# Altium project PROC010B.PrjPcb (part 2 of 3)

## Sheet PROC010C_Pwr_RST_LEDs.SchDoc: Pwr_RST_LEDs
size 431 x 279 mm; Date: Not shown in title block; ApprovedBy: Not shown in title block; CheckedBy: Not shown in title block; Author: Not shown in title block; CompanyName: Not shown in title block; DrawnBy: Adrian Ozer; Engineer: Not shown in title block; Organization: Not shown in title block; Address1: Not shown in title block; Address2: Not shown in title block; Address3: Not shown in title block; Address4: Not shown in title block; DocumentNumber: 8; Revision: Use project parameter SCH_Rev; SheetNumber: 8; SheetTotal: 16; PageSetup: Record=PageOptions¦CenterHorizontal=True¦CenterVertical=True¦PrintScale=1.00¦XCorrection=1.00¦YCorrection=1.00¦PrintKind=0¦BorderSize=5000000¦LeftOffset=0¦BottomOffset=0¦Orientation=2¦PaperLength=1000¦PaperWidth=1000¦Scale=100¦PaperSource=15¦PrintQuality=600¦MediaType=1¦DitherType=10¦PaperKind=Letter¦PrintScaleMode=1
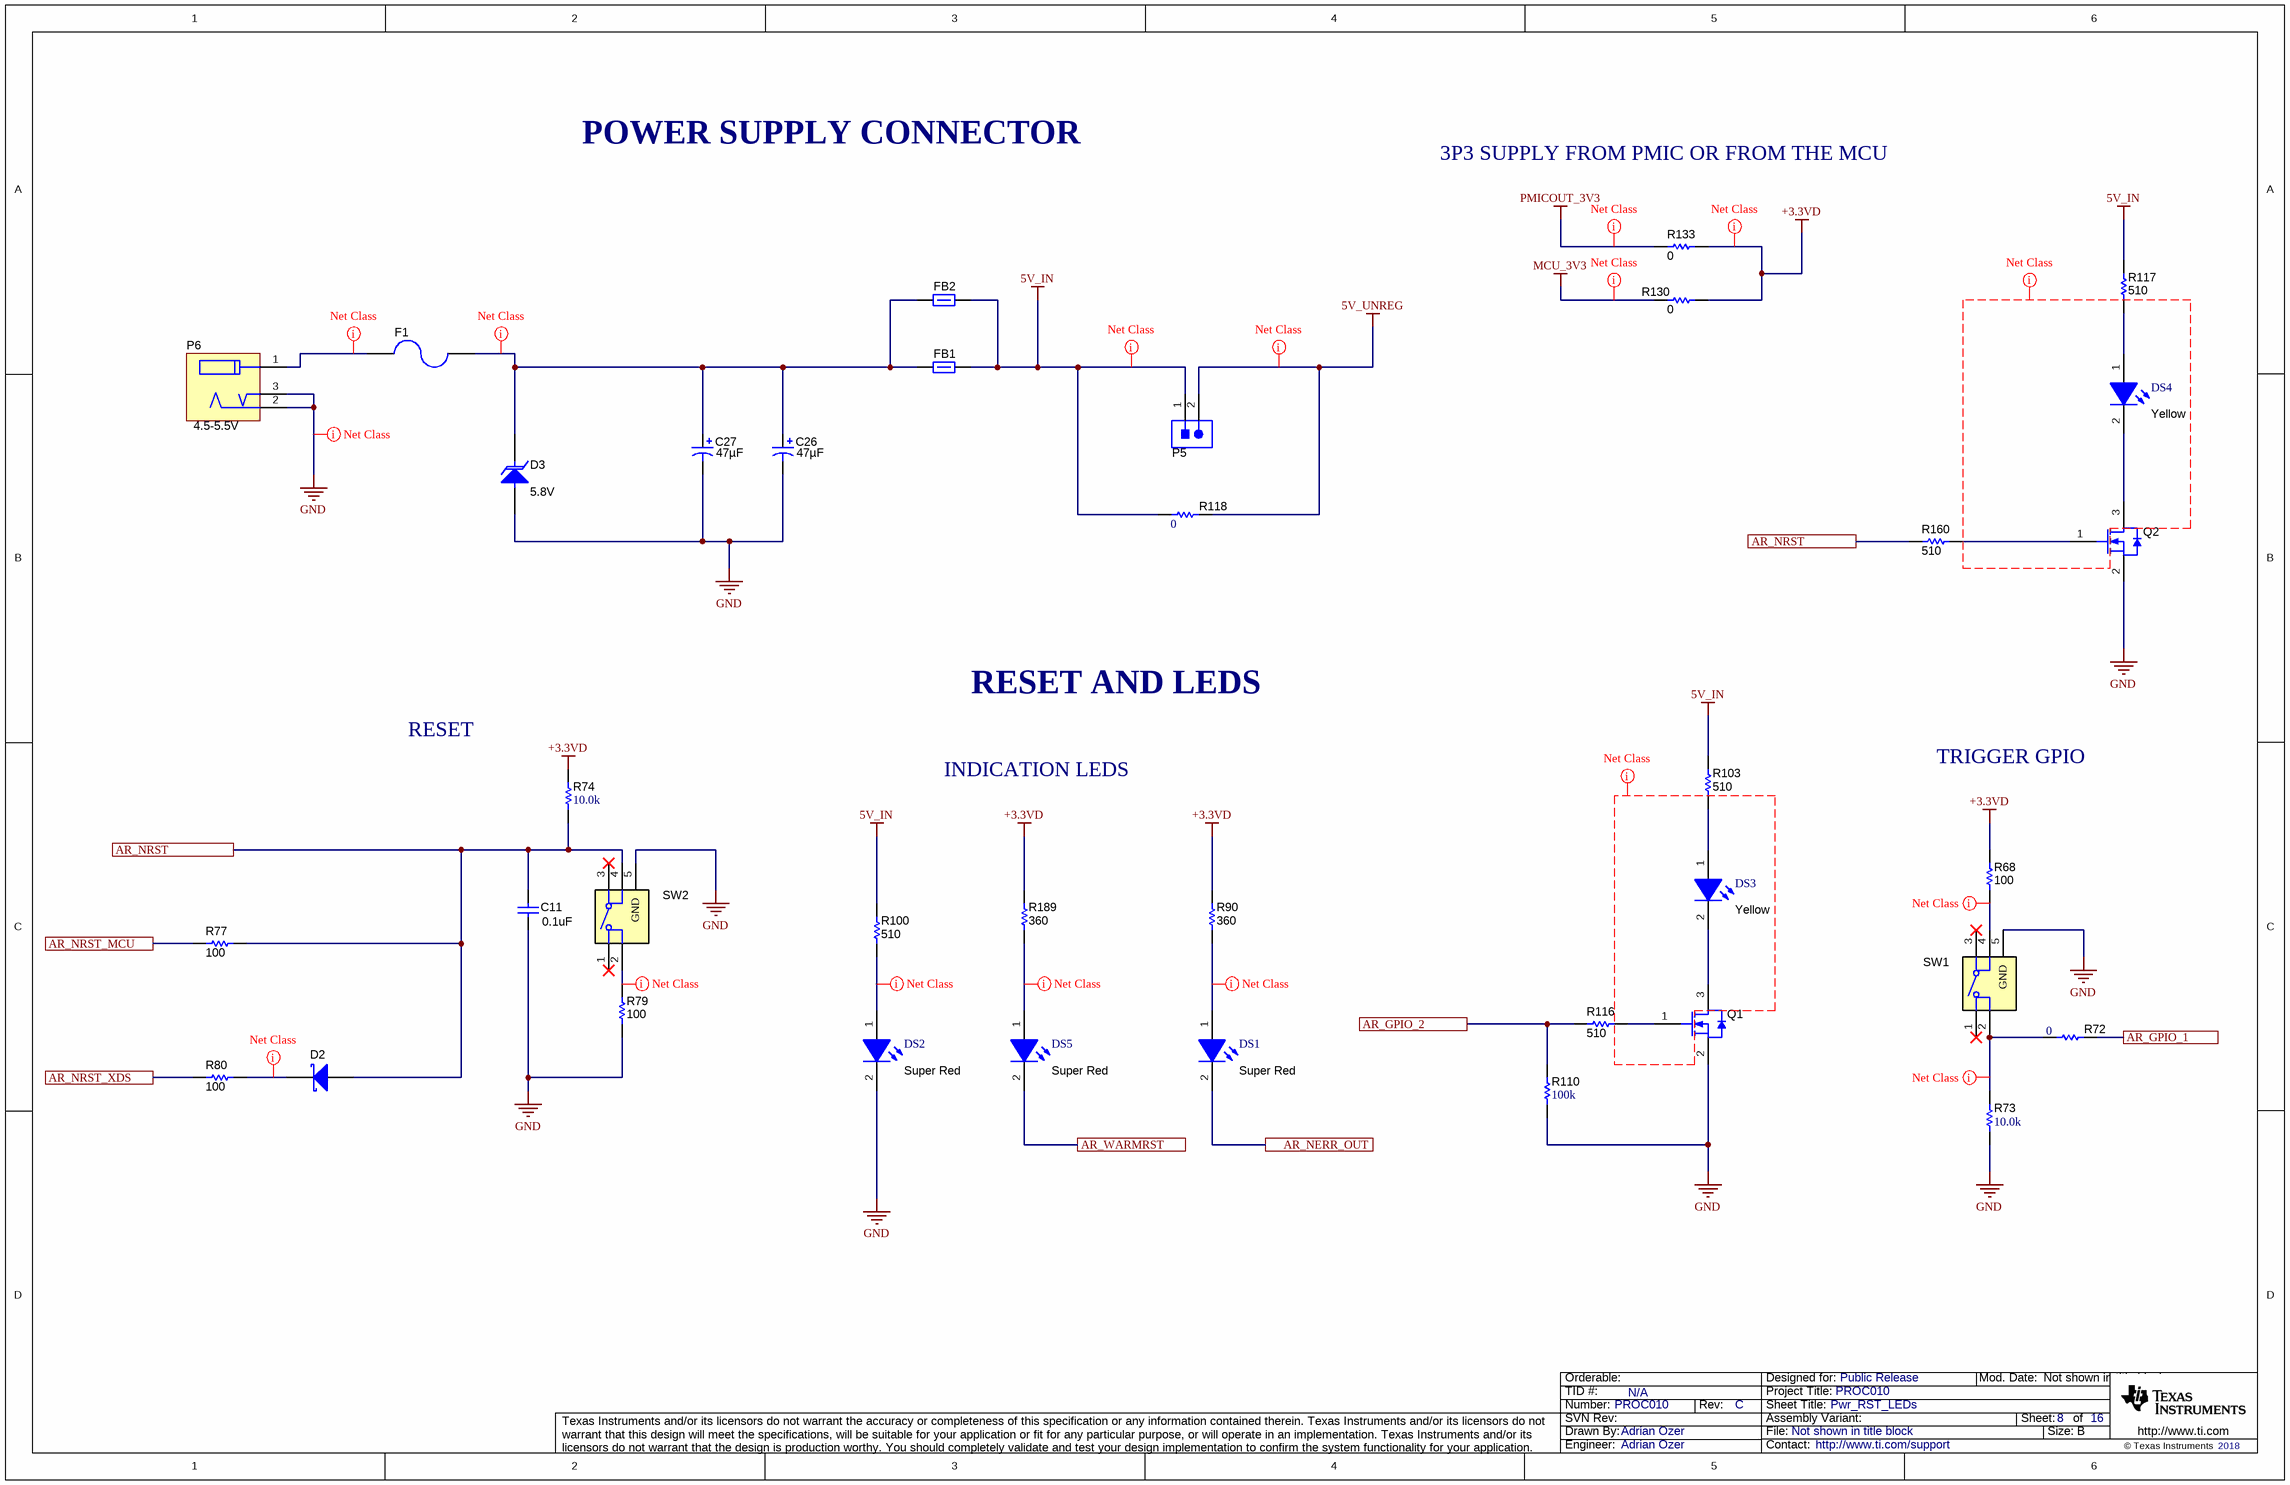
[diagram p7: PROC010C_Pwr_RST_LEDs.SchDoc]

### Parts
C11  ValueDisplayed: 0.1uF  [0402L]  (hidden comment: GCM155R71C104KA55D)
C26  ValueDisplayed: 47µF  [3528-21]  (hidden comment: T491B476K010AT)
C27  ValueDisplayed: 47µF  [3528-21]  (hidden comment: T491B476K010AT)
D2  SMS3923-040LF  [SOD-882]  (value not drawn)
D3  value 5.8V  [SMB]  (hidden comment: SZP6SMB6.8AT3G)
DS1  value Super Red  [SML-LX0603SRW_SuperRed]  (hidden comment: SML-LX0603SRW-TR)
DS2  value Super Red  [SML-LX0603SRW_SuperRed]  (hidden comment: SML-LX0603SRW-TR)
DS3  value Yellow  [SML-E1_Yellow]  (hidden comment: SML-E12Y8WT86)
DS4  value Yellow  [SML-E1_Yellow]  (hidden comment: SML-E12Y8WT86)
DS5  value Super Red  [SML-LX0603SRW_SuperRed]  (hidden comment: SML-LX0603SRW-TR)
F1  0440005.WR  [1206]  (value not drawn)
FB1  BLM21PG300SH1D  [0805_HV]  (value not drawn)
FB2  BLM21PG300SH1D  [0805_HV]  (value not drawn)
P5  TSW-102-07-G-S  [TSW-102-07-G-S]  (value not drawn)
P6  Voltage_V: 4.5-5.5V  [CUI_PJ-002AH]  (hidden comment: PJ-002AH)
Q1  BSS123  [SOT-23]  (value not drawn)
Q2  BSS123  [SOT-23]  (value not drawn)
R68  ValueDisplayed: 100  [0402L]  (hidden comment: ERJ-2GEJ101X)
R72  ValueDisplayed: 0  [0201_Silk]  (hidden comment: CRCW02010000Z0ED)
R73  ValueDisplayed: 10.0k  [0402L]  (hidden comment: CRCW040210K0FKED)
R74  ValueDisplayed: 10.0k  [0402L]  (hidden comment: CRCW040210K0FKED)
R77  ValueDisplayed: 100  [0402L]  (hidden comment: ERJ-2GEJ101X)
R79  ValueDisplayed: 100  [0402L]  (hidden comment: ERJ-2GEJ101X)
R80  ValueDisplayed: 100  [0402L]  (hidden comment: ERJ-2GEJ101X)
R90  ValueDisplayed: 360  [0402L]  (hidden comment: ERJ-2GEJ361X)
R100  ValueDisplayed: 510  [0402L]  (hidden comment: ERJ-2GEJ511X)
R103  ValueDisplayed: 510  [0402L]  (hidden comment: ERJ-2GEJ511X)
R110  ValueDisplayed: 100k  [0402L]  (hidden comment: CRCW0402100KFKED)
R116  ValueDisplayed: 510  [0402L]  (hidden comment: ERJ-2GEJ511X)
R117  ValueDisplayed: 510  [0402L]  (hidden comment: ERJ-2GEJ511X)
R118  ValueDisplayed: 0  [2010]  (hidden comment: CRCW20100000Z0EF)
R130  ValueDisplayed: 0  [0603]  (hidden comment: MCT06030Z0000ZP500)
R133  ValueDisplayed: 0  [0603]  (hidden comment: MCT06030Z0000ZP500)
R160  ValueDisplayed: 510  [0402L]  (hidden comment: ERJ-2GEJ511X)
R189  ValueDisplayed: 360  [0402L]  (hidden comment: ERJ-2GEJ361X)
SW1  KMR243GLFG  [SW_KMR243GLFG]  (value not drawn)
SW2  KMR243GLFG  [SW_KMR243GLFG]  (value not drawn)

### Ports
AR_GPIO_1, AR_GPIO_2, AR_NERR_OUT, AR_NRST, AR_NRST_MCU, AR_NRST_XDS, AR_WARMRST

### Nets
5V_IN: FB1.2 FB2.2 P5.1 R100.2 R103.2 R117.2 R118.1
5V_UNREG: P5.2 R118.2
+3.3VD: R68.2 R74.2 R90.2 R130.2 R133.2 R189.2
GND: C11.1 C26.2(-) C27.2(-) D3.2(A) DS2.2(K) P6.2 P6.3 Q1.2(S) Q2.2(S) R73.1 R79.1 R110.1 SW1.5(GND) SW2.5(GND)
MCU_3V3: R130.1
PMICOUT_3V3: R133.1
AR_GPIO_1: R72.2 ; port AR_GPIO_1
AR_GPIO_2: R110.2 R116.1 ; port AR_GPIO_2
AR_NERR_OUT: DS1.2(K) ; port AR_NERR_OUT
AR_NRST: C11.2 D2.2(A) R74.1 R77.2 R160.1 SW2.4 ; port AR_NRST
AR_NRST_MCU: R77.1 ; port AR_NRST_MCU
AR_NRST_XDS: R80.1 ; port AR_NRST_XDS
AR_WARMRST: DS5.2(K) ; port AR_WARMRST
NetC26_1: C26.1(+) C27.1(+) D3.1(K) F1.1 FB1.1 FB2.1
NetD2_1: D2.1(K) R80.2
NetDS1_1: DS1.1(A) R90.1
NetDS2_1: DS2.1(A) R100.1
NetDS3_1: DS3.1(A) R103.1
NetDS3_2: DS3.2(K) Q1.3(D)
NetDS4_1: DS4.1(A) R117.1
NetDS4_2: DS4.2(K) Q2.3(D)
NetDS5_1: DS5.1(A) R189.1
NetF1_2: F1.2 P6.1
NetQ1_1: Q1.1(G) R116.2
NetQ2_1: Q2.1(G) R160.2
NetR68_1: R68.1 SW1.4
NetR72_1: R72.1 R73.2 SW1.2
NetR79_2: R79.2 SW2.2

Not connected (* = marked no-connect by the designer): SW1 1* 3*; SW2 1* 3*

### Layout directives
net class PWR: 5V_IN, 5V_UNREG, +3.3VD, GND, MCU_3V3, NetC26_1, NetF1_2, PMICOUT_3V3
net class GENERAL: (no net found under the mark), NetD2_1, NetDS1_1, NetDS2_1, NetDS5_1, NetR68_1, NetR72_1, NetR79_2

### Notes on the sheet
- POWER SUPPLY CONNECTOR
- 3P3 SUPPLY FROM PMIC OR FROM THE MCU
- RESET AND LEDS
- RESET
- TRIGGER GPIO
- INDICATION LEDS

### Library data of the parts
C11 = CMP-0006351-2: CAP, CERM, 0.1 uF, 16 V, +/- 10%, X7R, 0402; Manufacturer: MuRata; TaMin_C: -55°C; Polarized: N; SizeAreaWB_mm2: 3; Value1: Unknown; U/M: EA; Value: 0.1uF; TaMax_C: 125°C; SizeZ_mm: 0.6; SizeX_mm: 1; SizeY_mm: 0.5; Cap_Case: 0402; Value2: 16V; Cap_F: 100nF; AEC Category: Q200
C26 C27 = CMP-0078216-1: CAP, TA, 47 µF, 10 V, +/- 10%, SMD; Manufacturer: Kemet; TaMin_C: -55°C; Polarized: Y; SizeAreaWB_mm2: 17.1; Value: 47uF; TaMax_C: 125°C; SizeZ_mm: 2.1; SizeX_mm: 3.5; SizeY_mm: 2.8; Value2: 10V; SizeArea_mm2: 9.8; CompType: Capacitor; AEC Qualified: N; AEC Category: Q200
D2 = CMP-0078187-1: Diode, Schottky,  V, 0.01 A, SOD-882; Manufacturer: Skyworks Solutions; SizeAreaWB_mm2: 3.2; SizeArea_mm2: 0.6; AEC Qualified: N; TJmax_C: 150°C; AEC Category: Q101; SizeZ_mm: 0.5; Io_A: 10mA; Vf_V: 3.4dV; Value2: 0.34V; Value1: 0.01A; SizeX_mm: 1
D3 = CMP-0078243-1: Diode, TVS, Uni, 5.8 V, 10.5 Vc, AEC-Q101, SMB; Manufacturer: Littelfuse; Power_W: 550mW; SizeAreaWB_mm2: 44.156; Value1: 0.55W; RJA_CperW: 226; SizeZ_mm: 2.6; SizeX_mm: 5.6; SizeY_mm: 3.81; SizeArea_mm2: 21.336; AEC Qualified: Y; AEC Category: Q101
DS1 DS2 DS5 = CMP-0002876-1: LED, Super Red, SMD; Manufacturer: Lumex; Io_A: 20mA; Value1: W; U/M: EA; Vf_V: 1.7V
DS3 DS4 = CMP-0002977-2: LED, Yellow, SMD; Manufacturer: Rohm; Io_A: 20mA; Power_TotalModule: 54mW; Vr_V: 5V; Tjmax_C: 85°C; Value1: 0.054W; U/M: EA; Ir_A: 10µA; Vf_V: 2.2V; LuminousIntensity_IV: 63
F1 = CMP-0003458-2: Fuse, 5 A, 32VAC/VDC, SMD; Manufacturer: Littelfuse; Irating_A: 5A; SizeAreaWB_mm2: 10.92; Interrupt_AC: 50A; VAC_V: 32V; SizeZ_mm: 1.35; SizeX_mm: 3.2; SizeY_mm: 1.6; SizeArea_mm2: 5.12; Rtyp_Ohm: 0.012; MeltingTyp: 4.761
FB1 = CMP-0003364-1: Ferrite Bead, 30 ohm @ 100 MHz, 4 A, 0805; Manufacturer: MuRata; ZTyp@100MHz_Ohm: 30; SizeAreaWB_mm2: 6.75; DCR_ohm: 0.014; Value1: 0.014 ohm; Value: 30 ohm; Imax_A: 4A; SizeZ_mm: 1.45; SizeX_mm: 2; SizeY_mm: 1.25; SizeArea_mm2: 2.5
FB2 = CMP-0003364-1: Ferrite Bead, 30 ohm @ 100 MHz, 4 A, 0805; Manufacturer: MuRata; ZTyp@100MHz_Ohm: 30; SizeAreaWB_mm2: 6.75; DCR_ohm: 0.014; Value1: 0.014 ohm; Value: 30 ohm; Imax_A: 4A; SizeZ_mm: 1.45; SizeX_mm: 2; SizeY_mm: 1.25; SizeArea_mm2: 2.5; INSTALLATION: DNP
P5 = CMP-0075405-2: Header, 100mil, 2x1, Gold, TH; Manufacturer: Samtec; Pitch_mm: 2.54; Cert_VDE: N; Gender: Male; Cert_CSA: Y; Voltage_V: 550V; Green_REACh: Passed; Current_A: 6.3A; Green_Lifecycle: Active; Row_Count: 1
P6 = CMP-0078270-1: DC POWER JACK, R/A, TH; Manufacturer: CUI Inc.; Gender: Female; Cert_UL: Y; Current_A: 5A; Green_REACh: Incomplete; Green_Lifecycle: Not Set
Q1 Q2 = CMP-0000947-2: MOSFET, N-CH, 100 V, 0.17 A, SOT-23; Alternate Manufacturer: None; Manufacturer: Fairchild Semiconductor; SizeZ_mm: 1.1; ChType: N; Value2: 1.8 nC; Value1: 1; VdsMax_V: 100V; SizeX_mm: 2.5; SizeY_mm: 3; Vgs_V: 20V; Value: 100V; Rdson45_ohm: 10; SizeArea_mm2: 7.5; AEC Category: Q101; IdsMax_A: 1.7dA; SizeAreaWB_mm2: 14; U/M: EA; QgTyp_nC: 1.8
R68 R77 R79 R80 = CMP-0026993-2: RES, 100, 5%, 0.1 W, AEC-Q200 Grade 0, 0402; Manufacturer: Panasonic; Power_W: 100mW; TempCo: 200 ppm/C; Value_Code: 100R; U/M: EA; Value: 100; EIA_Code: E24; SizeX_mm: 1; SizeY_mm: 0.5; SizeZ_mm: 0.6; Value2: 0.1W; AEC Qualified: Y; AEC Grade: 0; AEC Category: Q200
R72 = CMP-0027008-4: RES, 0, 5%, 0.05 W, 0201; Manufacturer: Vishay-Dale; Power_W: 50mW; TempCo: ppm/C; Value_Code: 0000; Value: 0; EIA_Code: E24; SizeX_mm: 0.6; SizeY_mm: 0.3; SizeZ_mm: 0.26; Value2: 0.05W; SizeArea_mm2: 0.18; AEC Qualified: N; AEC Category: Q200
R73 R74 = CMP-0025958-3: RES, 10.0 k, 1%, 0.063 W, AEC-Q200 Grade 0, 0402; Manufacturer: Vishay-Dale; Power_W: 63mW; TempCo: 100 ppm/C; Value_Code: 10k0; Value: 10.0k; EIA_Code: E96; Res_ohm: 10k; SizeX_mm: 1; SizeY_mm: 0.5; SizeZ_mm: 0.6; Value2: 0.063W; AEC Qualified: Y; VDC_V: 50V; AEC Category: Q200; AEC Grade: 0
R90 R189 = CMP-0078194-1: RES, 360, 5%, 0.1 W, AEC-Q200 Grade 0, 0402; Manufacturer: Panasonic; Value_Code: 360R; SizeArea_mm2: 0.5; AEC Qualified: Y; AEC Category: Q200; Value: 360; SizeZ_mm: 0.6; EIA_Code: E24; TempCo: 200 ppm/C; AEC Grade: 0; Power_W: 100mW; VDC_V: 50V; Value2: 0.1W; U/M: EA; SizeX_mm: 1
R100 R103 R116 R117 R160 = CMP-0078212-1: RES, 510, 5%, 0.1 W, AEC-Q200 Grade 0, 0402; Manufacturer: Panasonic; Value_Code: 510R; SizeArea_mm2: 0.5; AEC Qualified: Y; AEC Category: Q200; Value: 510; SizeZ_mm: 0.6; EIA_Code: E24; TempCo: 200 ppm/C; AEC Grade: 0; Power_W: 100mW; VDC_V: 50V; Value2: 0.1W; U/M: EA; SizeX_mm: 1
R110 = CMP-0025950-3: RES, 100 k, 1%, 0.063 W, AEC-Q200 Grade 0, 0402; Manufacturer: Vishay-Dale; Power_W: 63mW; TempCo: 100 ppm/C; Value: 100k; EIA_Code: E96; SizeX_mm: 1; SizeY_mm: 0.5; SizeZ_mm: 0.6; Value2: 0.063W; AEC Qualified: Y; VDC_V: 50V; AEC Category: Q200; AEC Grade: 0
R118 = CMP-0016044-3: RES, 0, 5%, 0.75 W, AEC-Q200 Grade 0, 2010; Manufacturer: Vishay-Dale; Power_W: 750mW; TempCo: ppm/C; Value_Code: 0000; Value: 0; EIA_Code: E24; SizeX_mm: 5; SizeY_mm: 2.5; SizeZ_mm: 1.66; Value2: 0.75W; SizeArea_mm2: 12.5; AEC Qualified: Y; AEC Category: Q200
R130 = CMP-0025884-3: RES, 0, 5%, 0.125 W, 0603; Manufacturer: Vishay/Beyschlag; Power_W: 125mW; TempCo: ppm/C; Value_Code: 0000; U/M: EA; Value: 0; EIA_Code: E24; SizeX_mm: 1.6; SizeY_mm: 0.8; SizeZ_mm: 1; Value2: 0.125W; SizeArea_mm2: 1.28; CompType: Resistor; AEC Qualified: N; AEC Category: Q200; INSTALATION: DNP
R133 = CMP-0025884-3: RES, 0, 5%, 0.125 W, 0603; Manufacturer: Vishay/Beyschlag; Power_W: 125mW; TempCo: ppm/C; Value_Code: 0000; U/M: EA; Value: 0; EIA_Code: E24; SizeX_mm: 1.6; SizeY_mm: 0.8; SizeZ_mm: 1; Value2: 0.125W; SizeArea_mm2: 1.28; AEC Qualified: N; AEC Category: Q200
SW1 SW2 = CMP-0002325-1: Switch, SPST-NO, Off-Mom, 0.01 A, 32 VDC, SMD; Manufacturer: C&K Components; CurrentRating_mA: 10A; PositionCount: 1; SizeX_mm: 4.6; SizeY_mm: 2.8; SizeZ_mm: 1.9; SizeArea_mm2: 12.88; VDC_V: 32V; SizeAreaWB_mm2: 21.28

## Sheet PROC010C_LDO.SchDoc
size 431 x 279 mm; Date: Not shown in title block; ApprovedBy: Not shown in title block; CheckedBy: Not shown in title block; Author: Not shown in title block; CompanyName: Not shown in title block; DrawnBy: Adrian Ozer; Engineer: Not shown in title block; Organization: Not shown in title block; Address1: Not shown in title block; Address2: Not shown in title block; Address3: Not shown in title block; Address4: Not shown in title block; DocumentNumber: 9; Revision: Use project parameter SCH_Rev; SheetNumber: 9; SheetTotal: 16; PageSetup: Record=PageOptions¦CenterHorizontal=True¦CenterVertical=True¦PrintScale=1.00¦XCorrection=1.00¦YCorrection=1.00¦PrintKind=0¦BorderSize=5000000¦LeftOffset=0¦BottomOffset=0¦Orientation=2¦PaperLength=1000¦PaperWidth=1000¦Scale=100¦PaperSource=15¦PrintQuality=600¦MediaType=1¦DitherType=10¦PaperKind=Letter¦PrintScaleMode=1
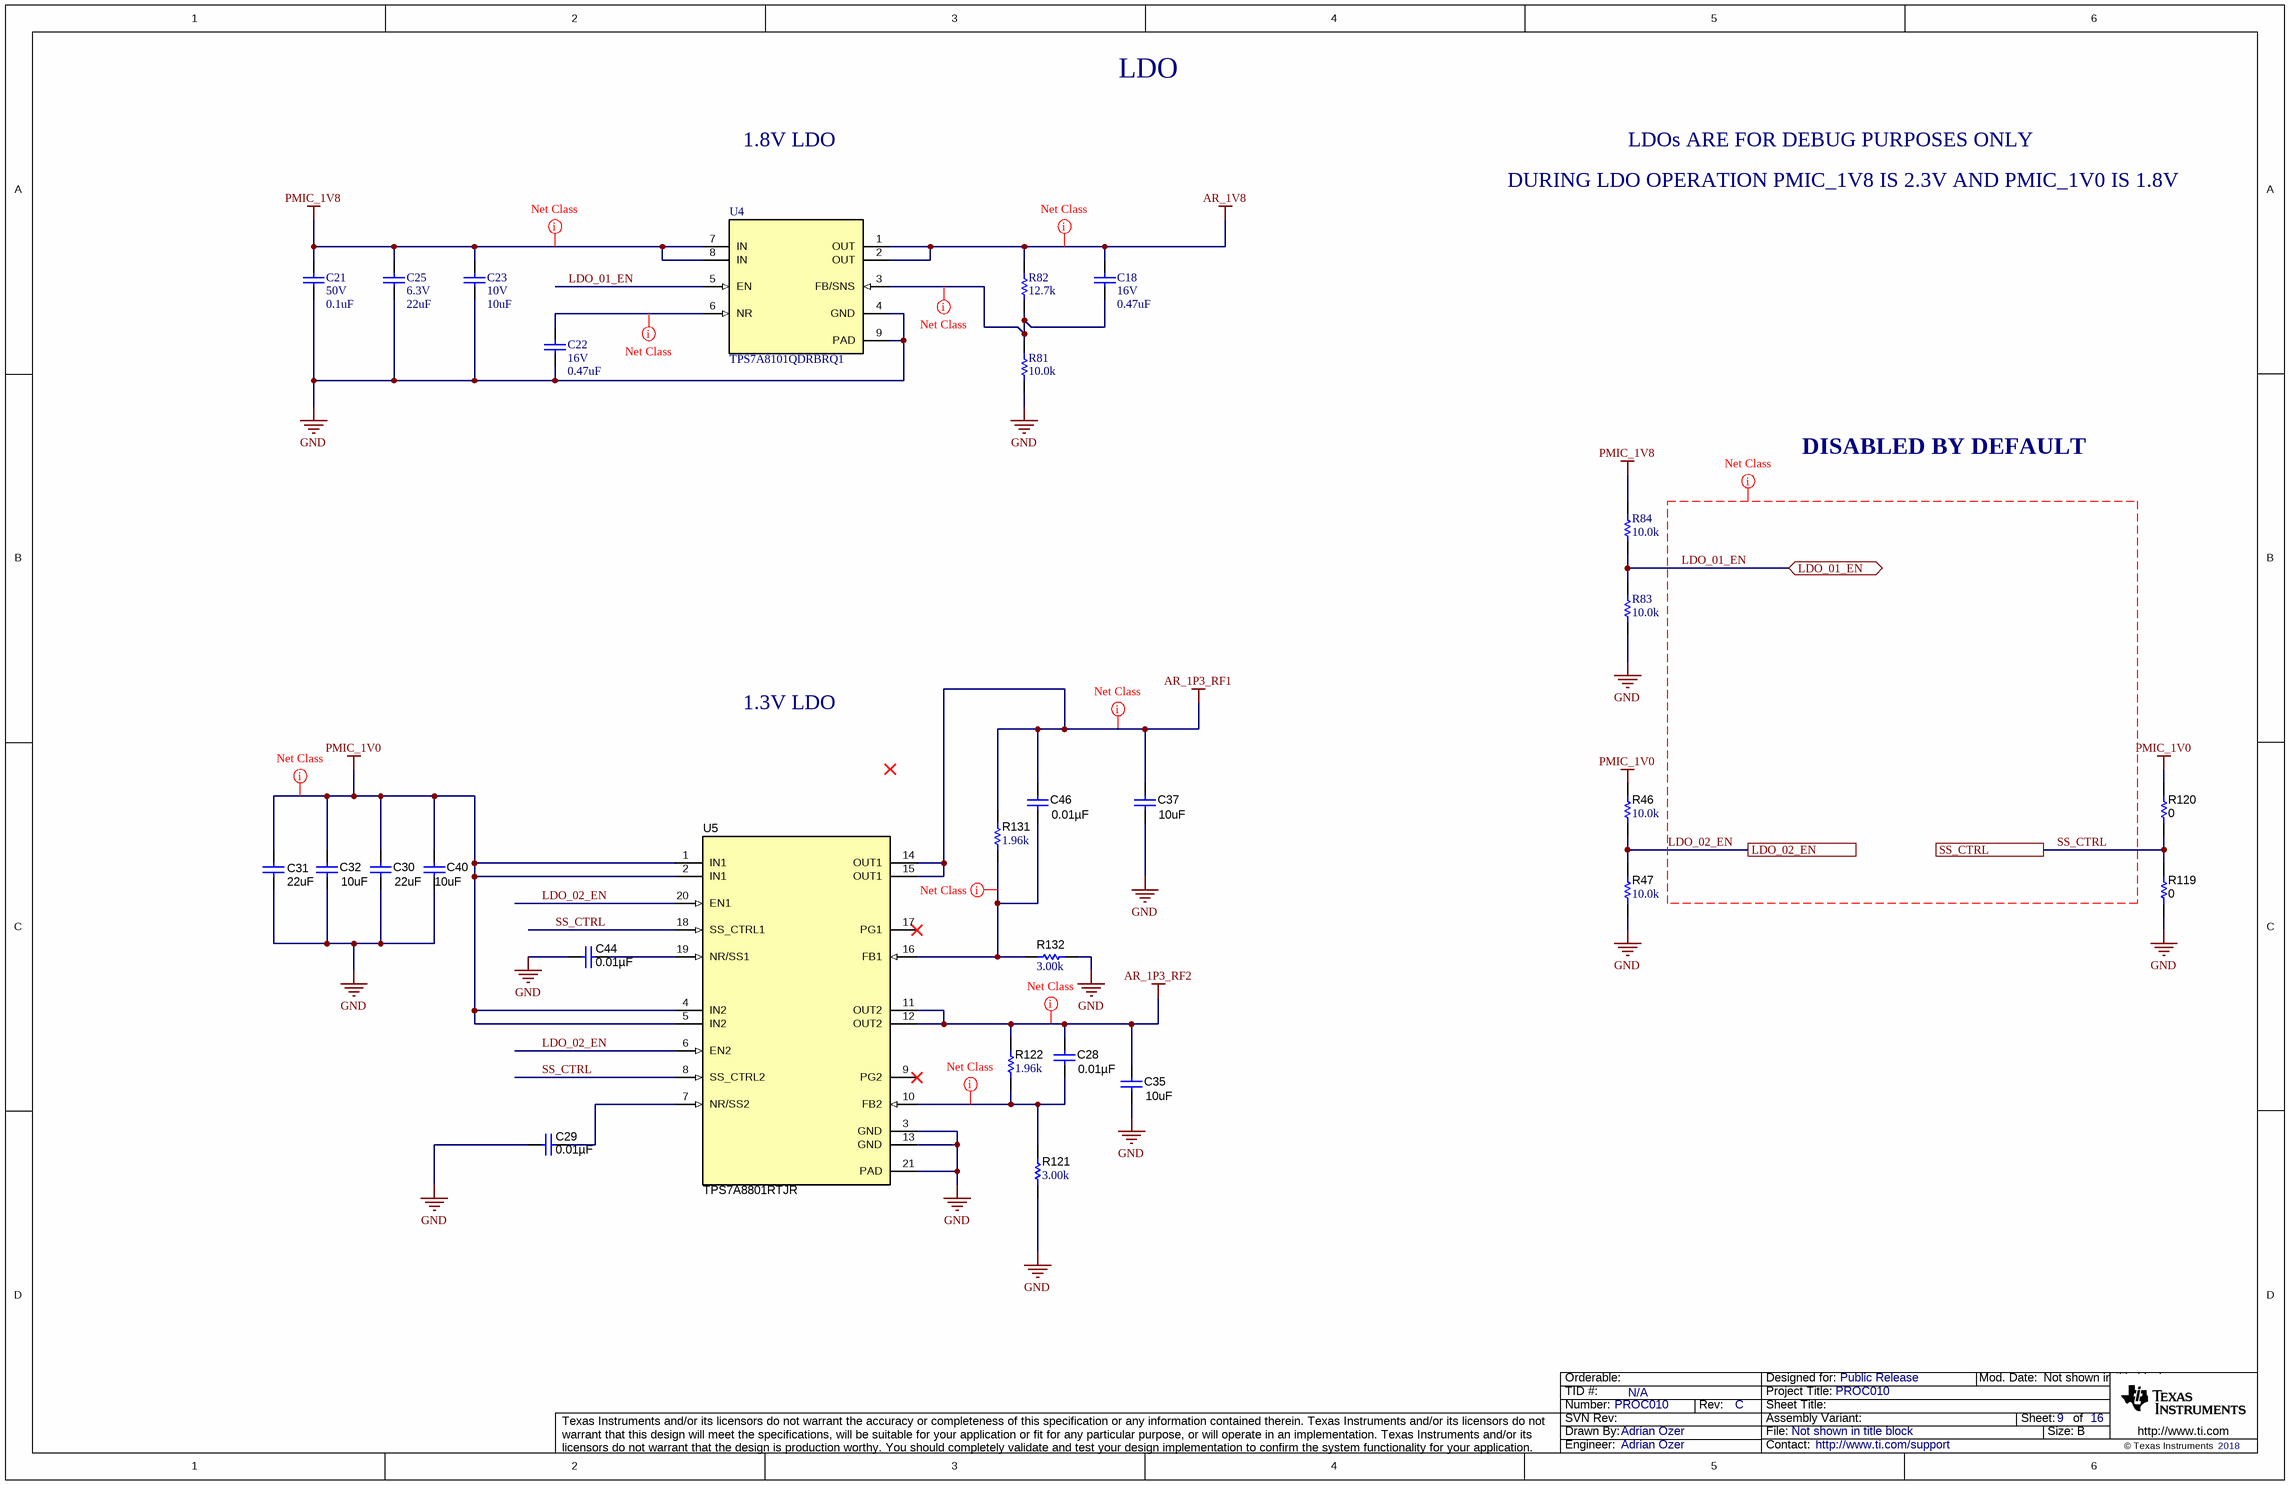
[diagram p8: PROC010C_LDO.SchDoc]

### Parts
C18  VDC_V: 16V  ValueDisplayed: 0.47uF  [0603]  (hidden comment: GCM188R71C474KA55D)
C21  VDC_V: 50V  ValueDisplayed: 0.1uF  [0402]  (hidden comment: CGA2B3X7R1H104K050BB)
C22  VDC_V: 16V  ValueDisplayed: 0.47uF  [0603]  (hidden comment: GCM188R71C474KA55D)
C23  VDC_V: 10V  ValueDisplayed: 10uF  [0805_HV]  (hidden comment: GCM21BR71A106KE22L)
C25  VDC_V: 6.3V  ValueDisplayed: 22uF  [1206_180]  (hidden comment: CGA5L1X7R0J226M160AC)
C28  ValueDisplayed: 0.01µF  [0402L]  (hidden comment: CGA2B3X8R1H103K050BB)
C29  ValueDisplayed: 0.01µF  [0402L]  (hidden comment: CGA2B3X8R1H103K050BB)
C30  ValueDisplayed: 22uF  [1206_180]  (hidden comment: CGA5L1X7R0J226M160AC)
C31  ValueDisplayed: 22uF  [1206_180]  (hidden comment: CGA5L1X7R0J226M160AC)
C32  ValueDisplayed: 10uF  [0805]  (hidden comment: GCM21BR71A106KE22L)
C35  ValueDisplayed: 10uF  [0805_HV]  (hidden comment: GCM21BR71A106KE22L)
C37  ValueDisplayed: 10uF  [0805_HV]  (hidden comment: GCM21BR71A106KE22L)
C40  ValueDisplayed: 10uF  [0805_HV1]  (hidden comment: GCM21BR71A106KE22L)
C44  ValueDisplayed: 0.01µF  [0402L]  (hidden comment: CGA2B3X8R1H103K050BB)
C46  ValueDisplayed: 0.01µF  [0402L]  (hidden comment: CGA2B3X8R1H103K050BB)
R46  ValueDisplayed: 10.0k  [0402L]  (hidden comment: CRCW040210K0FKED)
R47  ValueDisplayed: 10.0k  [0402L]  (hidden comment: CRCW040210K0FKED)
R81  ValueDisplayed: 10.0k  [0402L]  (hidden comment: CRCW040210K0FKED)
R82  ValueDisplayed: 12.7k  [0402L]  (hidden comment: CRCW040212K7FKED)
R83  ValueDisplayed: 10.0k  [0402]  (hidden comment: CRCW040210K0FKED)
R84  ValueDisplayed: 10.0k  [0402]  (hidden comment: CRCW040210K0FKED)
R119  ValueDisplayed: 0  [0402L]  (hidden comment: ERJ-2GE0R00X)
R120  ValueDisplayed: 0  [0402L]  (hidden comment: ERJ-2GE0R00X)
R121  ValueDisplayed: 3.00k  [0402L]  (hidden comment: CRCW04023K00FKED)
R122  ValueDisplayed: 1.96k  [0402L]  (hidden comment: CRCW04021K96FKED)
R131  ValueDisplayed: 1.96k  [0402L]  (hidden comment: CRCW04021K96FKED)
R132  ValueDisplayed: 3.00k  [0402L]  (hidden comment: CRCW04023K00FKED)
U4  TPS7A8101QDRBRQ1  [DRB0008A]
U5  TPS7A8801RTJR  [RTJ0020D]

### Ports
LDO_01_EN (bidir), LDO_02_EN, SS_CTRL

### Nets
AR_1P3_RF1: C37.2 C46.2 R131.2 U5.14(OUT1) U5.15(OUT1)
AR_1P3_RF2: C28.2 C35.2 R122.2 U5.11(OUT2) U5.12(OUT2)
AR_1V8: C18.1 R82.2 U4.1(OUT) U4.2(OUT)
GND: C21.2 C22.2 C23.2 C25.2 C29.1 C30.1 C31.1 C32.1 C35.1 C37.1 C40.1 C44.1 R47.2 R81.1 R83.1 R119.1 R121.1 R132.1 U4.4(GND) U4.9(PAD) U5.3(GND) U5.13(GND) U5.21(PAD)
PMIC_1V0: C30.2 C31.2 C32.2 C40.2 R46.1 R120.2 U5.1(IN1) U5.2(IN1) U5.4(IN2) U5.5(IN2)
PMIC_1V8: C21.1 C23.1 C25.1 R84.2 U4.7(IN) U4.8(IN)
LDO_01_EN: R83.2 R84.1 U4.5(EN) ; port LDO_01_EN
LDO_02_EN: R46.2 R47.1 U5.6(EN2) U5.20(EN1) ; port LDO_02_EN
SS_CTRL: R119.2 R120.1 U5.8(SS_CTRL2) U5.18(SS_CTRL1) ; port SS_CTRL
NetC18_2: C18.2 R81.2 R82.1 U4.3(FB/SNS)
NetC22_1: C22.1 U4.6(NR)
NetC28_1: C28.1 R121.2 R122.1 U5.10(FB2)
NetC29_2: C29.2 U5.7(NR/SS2)
NetC44_2: C44.2 U5.19(NR/SS1)
NetC46_1: C46.1 R131.1 R132.2 U5.16(FB1)

Not connected (* = marked no-connect by the designer): U5 9(PG2)* 17(PG1)*

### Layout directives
net class PWR: AR_1P3_RF1, AR_1P3_RF2, AR_1V8, NetC18_2, NetC28_1, NetC46_1, PMIC_1V0, PMIC_1V8
net class GENERAL: LDO_01_EN, LDO_02_EN, NetC22_1, SS_CTRL

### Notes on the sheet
- LDO
- 1.8V LDO
- LDOs ARE FOR DEBUG PURPOSES ONLY
- DURING LDO OPERATION PMIC_1V8 IS 2.3V AND PMIC_1V0 IS 1.8V
- DISABLED BY DEFAULT
- 1.3V LDO

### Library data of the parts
C18 C22 = CMP-0007138-4: CAP, CERM, 0.47 uF, 16 V, +/- 10%, X7R, AEC-Q200 Grade 1, 0603; Manufacturer: MuRata; TaMin_C: -55°C; Polarized: N; SizeAreaWB_mm2: 4.68; Value1: Unknown; U/M: EA; Value: 0.47uF; TaMax_C: 125°C; SizeZ_mm: 1; SizeX_mm: 1.6; SizeY_mm: 0.8; SizeArea_mm2: 1.28; AEC Qualified: Y; Cap_F: 470nF; AEC Category: Q200
C21 = CMP-0006325-2: CAP, CERM, 0.1 uF, 50 V, +/- 10%, X7R, AEC-Q200 Grade 1, 0402; Manufacturer: TDK; TaMin_C: -55°C; ESR_ohm: 0.039064; Polarized: N; SizeAreaWB_mm2: 3; Value1: 0.039064 ohm; U/M: EA; Value: 0.1uF; TaMax_C: 125°C; SizeZ_mm: 0.6; SizeX_mm: 1; SizeY_mm: 0.5; AEC Qualified: Y; Cap_F: 100nF; IRMS_A: 8.14669dA; AEC Category: Q200
C23 = CMP-0008017-2: CAP, CERM, 10 uF, 10 V, +/- 10%, X7R, 0805; Manufacturer: MuRata; TaMin_C: -55°C; Polarized: N; SizeAreaWB_mm2: 6.75; Value1: Unknown; U/M: EA; Value: 10uF; TaMax_C: 125°C; SizeZ_mm: 1.45; SizeX_mm: 2; SizeY_mm: 1.25; Cap_Case: 0805; SizeArea_mm2: 2.5; Cap_F: 10µF; AEC Category: Q200
C25 = CMP-0008770-2: CAP, CERM, 22 uF, 6.3 V, +/- 10%, X7R, AEC-Q200 Grade 1, 1206; Manufacturer: TDK; TaMin_C: -55°C; ESR_ohm: 1.872m; Polarized: N; SizeAreaWB_mm2: 10.92; Value1: 0.001872 ohm; U/M: EA; Value: 22uF; SizeZ_mm: 1.8; SizeX_mm: 3.2; SizeY_mm: 1.6; SizeArea_mm2: 5.12; AEC Qualified: Y; Cap_F: 22µF; IRMS_A: 5.30203A; AEC Grade: 1; AEC Category: Q200; TaMax_C: 125°C
C28 C29 C44 C46 = CMP-0078224-1: CAP, CERM, 0.01 µF, 50 V,+/- 10%, X8R, AEC-Q200 Grade 0, 0402; Manufacturer: TDK; TaMin_C: -55°C; Polarized: N; SizeAreaWB_mm2: 3; U/M: EA; Value: 0.01uF; TaMax_C: 150°C; SizeZ_mm: 0.6; SizeX_mm: 1; SizeY_mm: 0.5; Cap_Case: 0402; Value2: 50V; AEC Qualified: Y; Cap_F: 10nF; AEC Grade: 0; AEC Category: Q200
C30 C31 = CMP-0008770-2: CAP, CERM, 22 uF, 6.3 V, +/- 10%, X7R, AEC-Q200 Grade 1, 1206; Manufacturer: TDK; TaMin_C: -55°C; ESR_ohm: 1.872m; Polarized: N; SizeAreaWB_mm2: 10.92; Value1: 0.001872 ohm; U/M: EA; Value: 22uF; SizeZ_mm: 1.8; SizeX_mm: 3.2; SizeY_mm: 1.6; Value2: 6.3V; SizeArea_mm2: 5.12; AEC Qualified: Y; Cap_F: 22µF; IRMS_A: 5.30203A; AEC Grade: 1; AEC Category: Q200; TaMax_C: 125°C
C32 = CMP-0008017-2: CAP, CERM, 10 uF, 10 V, +/- 10%, X7R, 0805; Manufacturer: MuRata; TaMin_C: -55°C; Polarized: N; SizeAreaWB_mm2: 6.75; Value1: Unknown; U/M: EA; Value: 10uF; TaMax_C: 125°C; SizeZ_mm: 1.45; SizeX_mm: 2; SizeY_mm: 1.25; Value2: 10V; SizeArea_mm2: 2.5; CompType: Capacitor; Cap_F: 10µF; AEC Category: Q200
C35 C37 C40 = CMP-0008017-2: CAP, CERM, 10 uF, 10 V, +/- 10%, X7R, 0805; Manufacturer: MuRata; TaMin_C: -55°C; Polarized: N; SizeAreaWB_mm2: 6.75; Value1: Unknown; U/M: EA; Value: 10uF; TaMax_C: 125°C; SizeZ_mm: 1.45; SizeX_mm: 2; SizeY_mm: 1.25; Cap_Case: 0805; Value2: 10V; SizeArea_mm2: 2.5; CompType: Capacitor; Cap_F: 10µF; AEC Category: Q200
R46 R47 R83 R84 = CMP-0025958-3: as R73 on sheet PROC010C_Pwr_RST_LEDs
R81 = CMP-0025958-3: RES, 10.0 k, 1%, 0.063 W, AEC-Q200 Grade 0, 0402; Manufacturer: Vishay-Dale; Power_W: 63mW; TempCo: 100 ppm/C; Value_Code: 10k0; Value: 10.0k; EIA_Code: E96; Res_ohm: 10k; SizeX_mm: 1; SizeY_mm: 0.5; SizeZ_mm: 0.6; Value2: 0.063W; CompType: Resistor; AEC Qualified: Y; VDC_V: 50V; AEC Category: Q200; AEC Grade: 0
R82 = CMP-0025993-3: RES, 12.7 k, 1%, 0.063 W, AEC-Q200 Grade 0, 0402; Manufacturer: Vishay-Dale; Power_W: 63mW; TempCo: 100 ppm/C; Value_Code: 12k7; Value: 12.7k; EIA_Code: E96; SizeX_mm: 1; SizeY_mm: 0.5; SizeZ_mm: 0.6; Value2: 0.063W; CompType: Resistor; AEC Qualified: Y; VDC_V: 50V; AEC Category: Q200; AEC Grade: 0
R119 = CMP-0026992-2: RES, 0, 5%, 0.063 W, 0402; Manufacturer: Panasonic; Power_W: 63mW; TempCo: 600 ppm/C; Value_Code: 0000; U/M: EA; Value: 0; EIA_Code: E24; SizeX_mm: 1; SizeY_mm: 0.5; SizeZ_mm: 0.6; Value2: 0.063W; VDC_V: 50V; AEC Category: Q200
R120 = CMP-0026992-2: RES, 0, 5%, 0.063 W, 0402; Manufacturer: Panasonic; Power_W: 63mW; TempCo: 600 ppm/C; Value_Code: 0000; U/M: EA; Value: 0; EIA_Code: E24; SizeX_mm: 1; SizeY_mm: 0.5; SizeZ_mm: 0.6; Value2: 0.063W; CompType: Resistor; VDC_V: 50V; AEC Category: Q200; INSTALATION: DNP
R121 R132 = CMP-0078211-2: RES, 3.00 k, 1%, 0.063 W, AEC-Q200 Grade 0, 0402; Manufacturer: Vishay-Dale; Value_Code: 3k00; SizeArea_mm2: 0.5; AEC Qualified: Y; AEC Category: Q200; Res_ohm: 3k; Value: 3.00k; SizeZ_mm: 0.6; TempCo: 100 ppm/C; AEC Grade: 0; Power_W: 63mW; VDC_V: 50V; Value2: 0.063W; SizeX_mm: 1
R122 R131 = CMP-0026099-2: RES, 1.96 k, 1%, 0.063 W, AEC-Q200 Grade 0, 0402; Manufacturer: Vishay-Dale; Power_W: 63mW; TempCo: 100 ppm/C; Value_Code: 1k96; Value: 1.96k; EIA_Code: E96; SizeX_mm: 1; SizeY_mm: 0.5; SizeZ_mm: 0.6; Value2: 0.063W; AEC Qualified: Y; VDC_V: 50V; AEC Category: Q200; AEC Grade: 0
U4 = CMP-0073870-2: Automotive Low-Noise, Wide-Bandwidth, High PSRR, Low-Dropout 1-A Linear Regulator, DRB0008A (VSON-8); Manufacturer: Texas Instruments; SizeZ_mm: 1.0; SizeX_mm: 3.0; SizeArea_mm2: 9.0; CompType: IC; U/M: EA; SizeAreaWB_mm2: 16.0
U5 = CMP-0073732-2: Dual, 1-A, Low Noise (3.8-uVRMS), LDO Voltage Regulator, RTJ0020D (WQFN-20); Alternate PartNumber: TPS7A8801RTJT; Alternate Manufacturer: Texas Instruments; Green_Lifecycle: Active; SizeAreaWB_mm2: 25.0; Green_REACh: Passed; U/M: EA; SizeZ_mm: 0.8; SizeX_mm: 4.0; SizeArea_mm2: 16.0; CompType: IC

## Sheet PROC010C_HD Connector.SchDoc: HD Connector
size 431 x 279 mm; Date: Not shown in title block; ApprovedBy: Not shown in title block; CheckedBy: Not shown in title block; Author: Not shown in title block; CompanyName: Not shown in title block; DrawnBy: Adrian Ozer; Engineer: Not shown in title block; Organization: Not shown in title block; Address1: Not shown in title block; Address2: Not shown in title block; Address3: Not shown in title block; Address4: Not shown in title block; DocumentNumber: 10; Revision: Use project parameter SCH_Rev; SheetNumber: 10; SheetTotal: 16; PageSetup: Record=PageOptions¦CenterHorizontal=True¦CenterVertical=True¦PrintScale=1.00¦XCorrection=1.00¦YCorrection=1.00¦PrintKind=0¦BorderSize=5000000¦LeftOffset=0¦BottomOffset=0¦Orientation=2¦PaperLength=1000¦PaperWidth=1000¦Scale=100¦PaperSource=15¦PrintQuality=600¦MediaType=1¦DitherType=10¦PrintScaleMode=1¦PaperKind=Letter
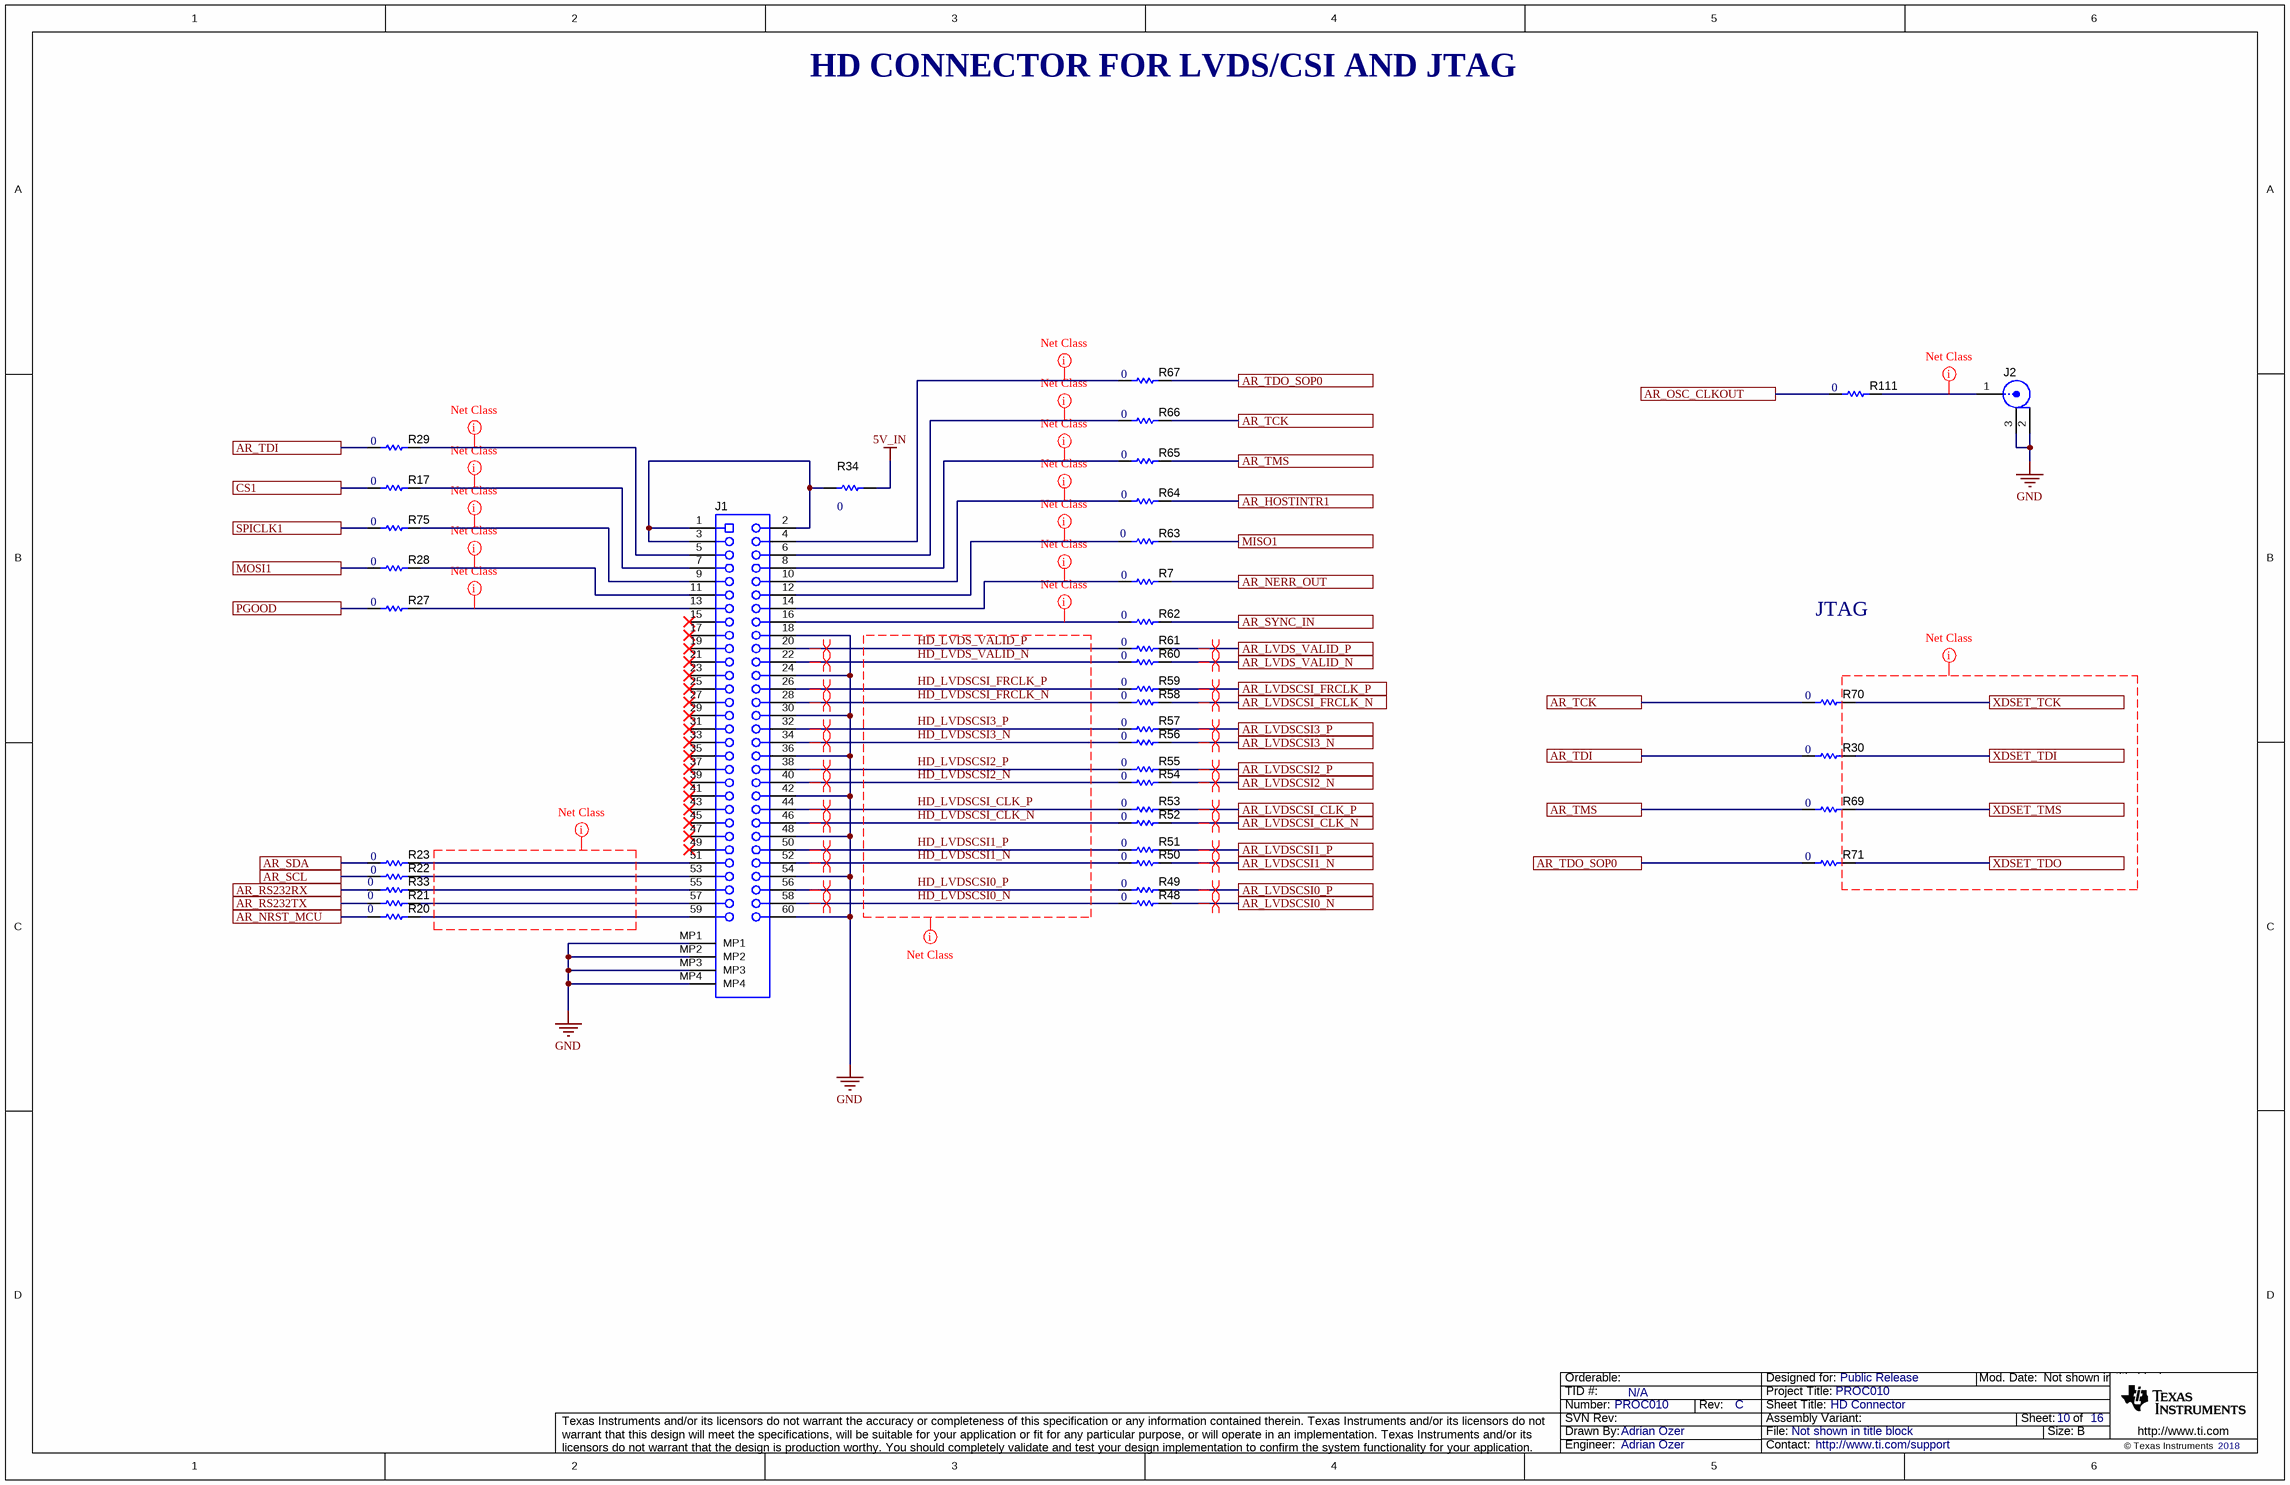
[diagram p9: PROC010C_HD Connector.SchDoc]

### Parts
J1  QSH-030-01-L-D-A  [Samtec_QSH-030-01-X-D-A]  (value not drawn)
J2  128-0711-201  [Johnson_128-0711-201]  (value not drawn)
R7  ValueDisplayed: 0  [0201_Silk]  (hidden comment: CRCW02010000Z0ED)
R17  ValueDisplayed: 0  [0201_Silk]  (hidden comment: CRCW02010000Z0ED)
R20  ValueDisplayed: 0  [0201_Silk]  (hidden comment: CRCW02010000Z0ED)
R21  ValueDisplayed: 0  [0201_Silk]  (hidden comment: CRCW02010000Z0ED)
R22  ValueDisplayed: 0  [0201_Silk]  (hidden comment: CRCW02010000Z0ED)
R23  ValueDisplayed: 0  [0201_Silk]  (hidden comment: CRCW02010000Z0ED)
R27  ValueDisplayed: 0  [0201_Silk]  (hidden comment: CRCW02010000Z0ED)
R28  ValueDisplayed: 0  [0201_Silk]  (hidden comment: CRCW02010000Z0ED)
R29  ValueDisplayed: 0  [0201_Silk]  (hidden comment: CRCW02010000Z0ED)
R30  ValueDisplayed: 0  [0201_Silk]  (hidden comment: CRCW02010000Z0ED)
R33  ValueDisplayed: 0  [0201_Silk]  (hidden comment: CRCW02010000Z0ED)
R34  ValueDisplayed: 0  [2010L]  (hidden comment: CRCW20100000Z0EF)
R48  ValueDisplayed: 0  [0201_Silk]  (hidden comment: CRCW02010000Z0ED)
R49  ValueDisplayed: 0  [0201_Silk]  (hidden comment: CRCW02010000Z0ED)
R50  ValueDisplayed: 0  [0201_Silk]  (hidden comment: CRCW02010000Z0ED)
R51  ValueDisplayed: 0  [0201_Silk]  (hidden comment: CRCW02010000Z0ED)
R52  ValueDisplayed: 0  [0201_Silk]  (hidden comment: CRCW02010000Z0ED)
R53  ValueDisplayed: 0  [0201_Silk]  (hidden comment: CRCW02010000Z0ED)
R54  ValueDisplayed: 0  [0201_Silk]  (hidden comment: CRCW02010000Z0ED)
R55  ValueDisplayed: 0  [0201_Silk]  (hidden comment: CRCW02010000Z0ED)
R56  ValueDisplayed: 0  [0201_Silk]  (hidden comment: CRCW02010000Z0ED)
R57  ValueDisplayed: 0  [0201_Silk]  (hidden comment: CRCW02010000Z0ED)
R58  ValueDisplayed: 0  [0201_Silk]  (hidden comment: CRCW02010000Z0ED)
R59  ValueDisplayed: 0  [0201_Silk]  (hidden comment: CRCW02010000Z0ED)
R60  ValueDisplayed: 0  [0201_Silk]  (hidden comment: CRCW02010000Z0ED)
R61  ValueDisplayed: 0  [0201_Silk]  (hidden comment: CRCW02010000Z0ED)
R62  ValueDisplayed: 0  [0201_Silk]  (hidden comment: CRCW02010000Z0ED)
R63  ValueDisplayed: 0  [0201_Silk]  (hidden comment: CRCW02010000Z0ED)
R64  ValueDisplayed: 0  [0201_Silk]  (hidden comment: CRCW02010000Z0ED)
R65  ValueDisplayed: 0  [0201_Silk]  (hidden comment: CRCW02010000Z0ED)
R66  ValueDisplayed: 0  [0201_Silk]  (hidden comment: CRCW02010000Z0ED)
R67  ValueDisplayed: 0  [0201_Silk]  (hidden comment: CRCW02010000Z0ED)
R69  ValueDisplayed: 0  [0201_Silk]  (hidden comment: CRCW02010000Z0ED)
R70  ValueDisplayed: 0  [0201_Silk]  (hidden comment: CRCW02010000Z0ED)
R71  ValueDisplayed: 0  [0201_Silk]  (hidden comment: CRCW02010000Z0ED)
R75  ValueDisplayed: 0  [0201_Silk]  (hidden comment: CRCW02010000Z0ED)
R111  ValueDisplayed: 0  [0201_Silk]  (hidden comment: CRCW02010000Z0ED)

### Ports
AR_HOSTINTR1, AR_LVDS_VALID_N, AR_LVDS_VALID_P, AR_LVDSCSI0_N, AR_LVDSCSI0_P, AR_LVDSCSI1_N, AR_LVDSCSI1_P, AR_LVDSCSI2_N, AR_LVDSCSI2_P, AR_LVDSCSI3_N, AR_LVDSCSI3_P, AR_LVDSCSI_CLK_N, AR_LVDSCSI_CLK_P, AR_LVDSCSI_FRCLK_N, AR_LVDSCSI_FRCLK_P, AR_NERR_OUT, AR_NRST_MCU, AR_OSC_CLKOUT, AR_RS232RX, AR_RS232TX, AR_SCL, AR_SDA, AR_SYNC_IN, AR_TCK, AR_TDI, AR_TDO_SOP0, AR_TMS, CS1, MISO1, MOSI1, PGOOD, SPICLK1, XDSET_TCK, XDSET_TDI, XDSET_TDO, XDSET_TMS

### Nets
5V_IN: R34.2
GND: J1.18 J1.24 J1.30 J1.36 J1.42 J1.48 J1.54 J1.60 J1.MP1 J1.MP2 J1.MP3 J1.MP4 J2.2 J2.3
AR_HOSTINTR1: R64.2 ; port AR_HOSTINTR1
AR_LVDS_VALID_N: R60.2 ; port AR_LVDS_VALID_N
AR_LVDS_VALID_P: R61.2 ; port AR_LVDS_VALID_P
AR_LVDSCSI0_N: R48.2 ; port AR_LVDSCSI0_N
AR_LVDSCSI0_P: R49.2 ; port AR_LVDSCSI0_P
AR_LVDSCSI1_N: R50.2 ; port AR_LVDSCSI1_N
AR_LVDSCSI1_P: R51.2 ; port AR_LVDSCSI1_P
AR_LVDSCSI2_N: R54.2 ; port AR_LVDSCSI2_N
AR_LVDSCSI2_P: R55.2 ; port AR_LVDSCSI2_P
AR_LVDSCSI3_N: R56.2 ; port AR_LVDSCSI3_N
AR_LVDSCSI3_P: R57.2 ; port AR_LVDSCSI3_P
AR_LVDSCSI_CLK_N: R52.2 ; port AR_LVDSCSI_CLK_N
AR_LVDSCSI_CLK_P: R53.2 ; port AR_LVDSCSI_CLK_P
AR_LVDSCSI_FRCLK_N: R58.2 ; port AR_LVDSCSI_FRCLK_N
AR_LVDSCSI_FRCLK_P: R59.2 ; port AR_LVDSCSI_FRCLK_P
AR_NERR_OUT: R7.2 ; port AR_NERR_OUT
AR_NRST_MCU: R20.1 ; port AR_NRST_MCU
AR_OSC_CLKOUT: R111.1 ; port AR_OSC_CLKOUT
AR_RS232RX: R33.1 ; port AR_RS232RX
AR_RS232TX: R21.1 ; port AR_RS232TX
AR_SCL: R22.1 ; port AR_SCL
AR_SDA: R23.1 ; port AR_SDA
AR_SYNC_IN: R62.2 ; port AR_SYNC_IN
AR_TCK: R66.2 R70.1 ; port AR_TCK
AR_TDI: R29.1 R30.1 ; port AR_TDI
AR_TDO_SOP0: R67.2 R71.1 ; port AR_TDO_SOP0
AR_TMS: R65.2 R69.1 ; port AR_TMS
CS1: R17.1 ; port CS1
HD_LVDS_VALID_N: J1.22 R60.1
HD_LVDS_VALID_P: J1.20 R61.1
HD_LVDSCSI0_N: J1.58 R48.1
HD_LVDSCSI0_P: J1.56 R49.1
HD_LVDSCSI1_N: J1.52 R50.1
HD_LVDSCSI1_P: J1.50 R51.1
HD_LVDSCSI2_N: J1.40 R54.1
HD_LVDSCSI2_P: J1.38 R55.1
HD_LVDSCSI3_N: J1.34 R56.1
HD_LVDSCSI3_P: J1.32 R57.1
HD_LVDSCSI_CLK_N: J1.46 R52.1
HD_LVDSCSI_CLK_P: J1.44 R53.1
HD_LVDSCSI_FRCLK_N: J1.28 R58.1
HD_LVDSCSI_FRCLK_P: J1.26 R59.1
MISO1: R63.2 ; port MISO1
MOSI1: R28.1 ; port MOSI1
PGOOD: R27.1 ; port PGOOD
SPICLK1: R75.1 ; port SPICLK1
XDSET_TCK: R70.2 ; port XDSET_TCK
XDSET_TDI: R30.2 ; port XDSET_TDI
XDSET_TDO: R71.2 ; port XDSET_TDO
XDSET_TMS: R69.2 ; port XDSET_TMS
NetJ1_1: J1.1 J1.2 J1.3 R34.1
NetJ1_4: J1.4 R67.1
NetJ1_5: J1.5 R29.2
NetJ1_6: J1.6 R66.1
NetJ1_7: J1.7 R17.2
NetJ1_8: J1.8 R65.1
NetJ1_9: J1.9 R75.2
NetJ1_10: J1.10 R64.1
NetJ1_11: J1.11 R28.2
NetJ1_12: J1.12 R63.1
NetJ1_13: J1.13 R27.2
NetJ1_14: J1.14 R7.1
NetJ1_16: J1.16 R62.1
NetJ1_51: J1.51 R23.2
NetJ1_53: J1.53 R22.2
NetJ1_55: J1.55 R33.2
NetJ1_57: J1.57 R21.2
NetJ1_59: J1.59 R20.2
NetJ2_1: J2.1 R111.2

Not connected (* = marked no-connect by the designer): J1 15* 17* 19* 21* 23* 25* 27* 29* 31* 33* 35* 37* 39* 41* 43* 45* 47* 49*

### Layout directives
net class GENERAL: (no net found under the mark), NetJ1_13, NetJ1_14, NetJ1_16
net class JTAG: (no net found under the mark), NetJ1_4, NetJ1_5, NetJ1_6, NetJ1_8
net class LVDS: HD_LVDS_VALID_N, HD_LVDS_VALID_P, HD_LVDSCSI0_N, HD_LVDSCSI0_P, HD_LVDSCSI1_N, HD_LVDSCSI1_P, HD_LVDSCSI2_N, HD_LVDSCSI2_P, HD_LVDSCSI3_N, HD_LVDSCSI3_P, HD_LVDSCSI_CLK_N, HD_LVDSCSI_CLK_P, HD_LVDSCSI_FRCLK_N, HD_LVDSCSI_FRCLK_P
net class CLK: NetJ2_1
net class SPI: NetJ1_7, NetJ1_9, NetJ1_10, NetJ1_11, NetJ1_12
differential pair: AR_LVDS_VALID_N, AR_LVDS_VALID_P, AR_LVDSCSI0_N, AR_LVDSCSI0_P, AR_LVDSCSI1_N, AR_LVDSCSI1_P, AR_LVDSCSI2_N, AR_LVDSCSI2_P, AR_LVDSCSI3_N, AR_LVDSCSI3_P, AR_LVDSCSI_CLK_N, AR_LVDSCSI_CLK_P, AR_LVDSCSI_FRCLK_N, AR_LVDSCSI_FRCLK_P, HD_LVDS_VALID_N, HD_LVDS_VALID_P, HD_LVDSCSI0_N, HD_LVDSCSI0_P, HD_LVDSCSI1_N, HD_LVDSCSI1_P, HD_LVDSCSI2_N, HD_LVDSCSI2_P, HD_LVDSCSI3_N, HD_LVDSCSI3_P, HD_LVDSCSI_CLK_N, HD_LVDSCSI_CLK_P, HD_LVDSCSI_FRCLK_N, HD_LVDSCSI_FRCLK_P

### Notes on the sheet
- HD CONNECTOR FOR LVDS/CSI AND JTAG
- JTAG

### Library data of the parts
J1 = CMP-0075524-1: Receptacle, 0.5 mm, 30x2, Gold, TH; Manufacturer: Samtec; Pitch_mm: 0.5; Gender: Female; Green_REACh: Passed; CT: False; Shrouded: N; RowSpacing_mm: 5.73; Green_Lifecycle: Active; Row_Count: 2
J2 = CMP-0055788-1: UMC Straight Jack Receptacle, 50 Ohm, Gold, SMT; Manufacturer: Cinch Connectivity; CNHeader: FALSE; Gender: Female
R7 R17 R20-R23 R27-R30 R33 R48-R67 R69-R71 R75 R111 = CMP-0027008-4: as R72 on sheet PROC010C_Pwr_RST_LEDs
R34 = CMP-0016044-3: RES, 0, 5%, 0.75 W, AEC-Q200 Grade 0, 2010; Manufacturer: Vishay-Dale; Power_W: 750mW; TempCo: ppm/C; Value_Code: 0000; Value: 0; EIA_Code: E24; SizeX_mm: 5; SizeY_mm: 2.5; SizeZ_mm: 1.66; Value2: 0.75W; SizeArea_mm2: 12.5; CompType: Resistor; AEC Qualified: Y; AEC Category: Q200

## Sheet PROC010C_LP Connector.SchDoc: LP Connector
size 431 x 279 mm; Date: Not shown in title block; ApprovedBy: Not shown in title block; CheckedBy: Not shown in title block; Author: Not shown in title block; CompanyName: Not shown in title block; DrawnBy: Adrian Ozer; Engineer: Not shown in title block; Organization: Not shown in title block; Address1: Not shown in title block; Address2: Not shown in title block; Address3: Not shown in title block; Address4: Not shown in title block; DocumentNumber: 11; Revision: Use project parameter SCH_Rev; SheetNumber: 11; SheetTotal: 16; PageSetup: Record=PageOptions¦CenterHorizontal=True¦CenterVertical=True¦PrintScale=1.00¦XCorrection=1.00¦YCorrection=1.00¦PrintKind=0¦BorderSize=5000000¦LeftOffset=0¦BottomOffset=0¦Orientation=2¦PaperLength=1000¦PaperWidth=1000¦Scale=100¦PaperSource=15¦PrintQuality=600¦MediaType=1¦DitherType=10¦PaperKind=Letter¦PrintScaleMode=1
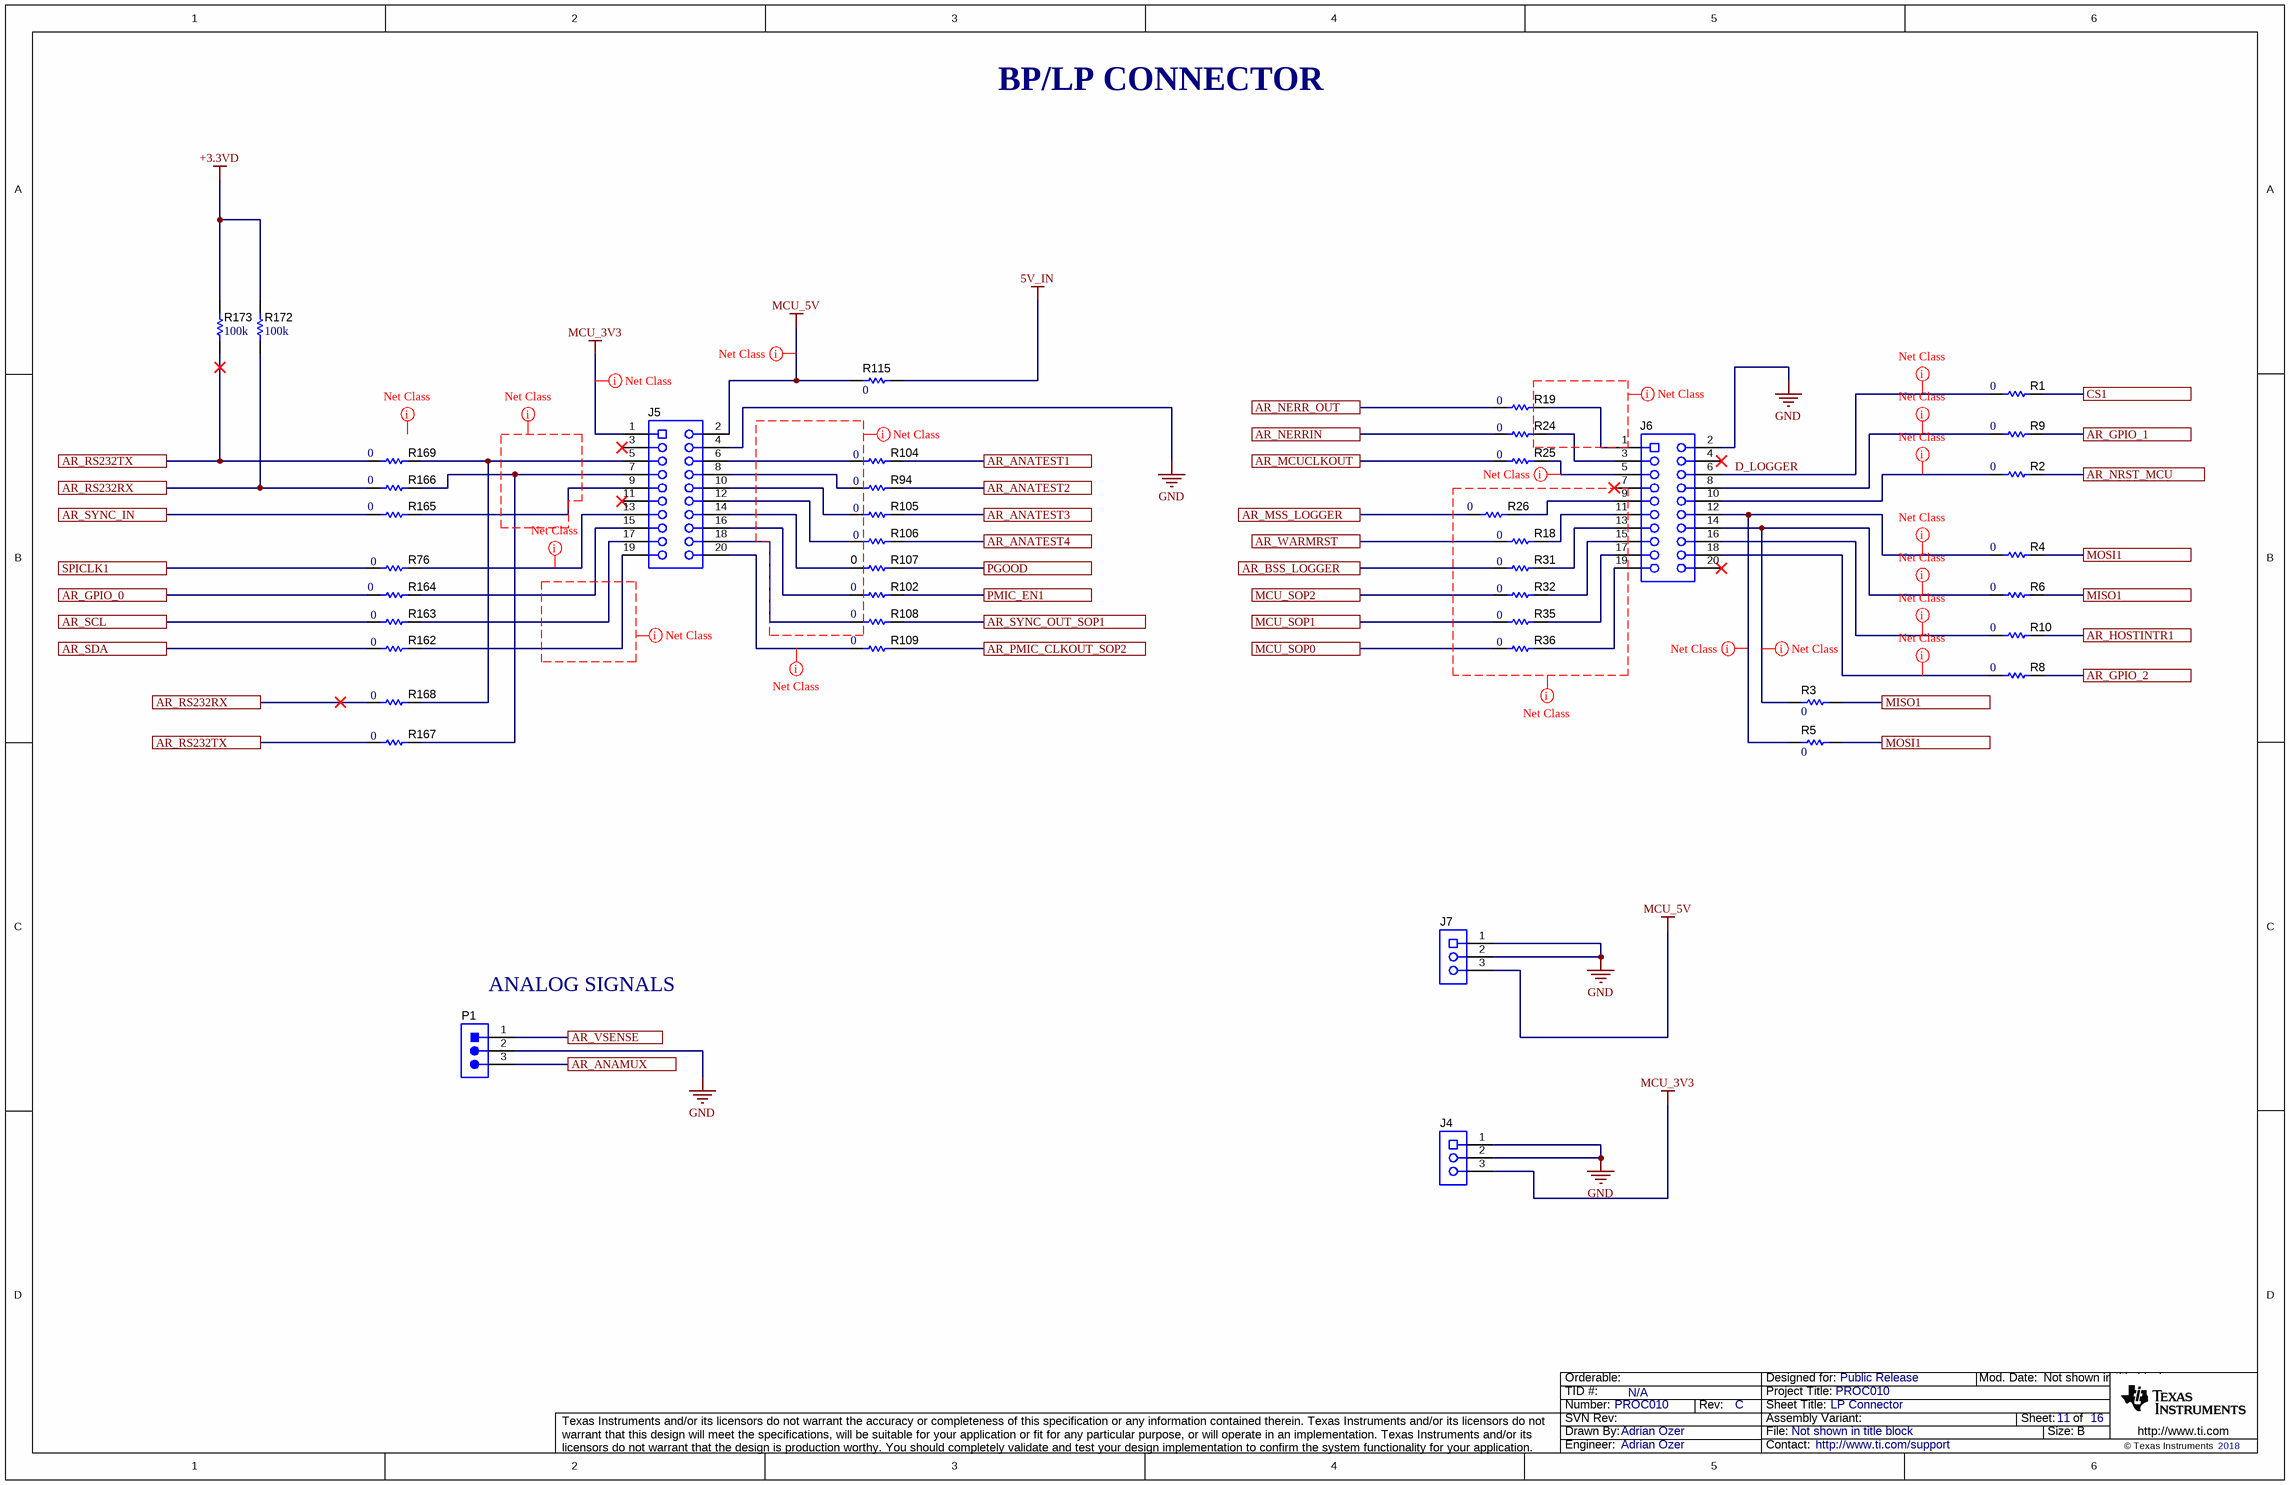
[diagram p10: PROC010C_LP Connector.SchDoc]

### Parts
J4  SSM-103-S-SV  [Samtec_SSM-103-x-SV]  (value not drawn)
J5  SSM-110-S-DV  [Samtec_SSM-110-x-DV]  (value not drawn)
J6  SSM-110-S-DV  [Samtec_SSM-110-x-DV]  (value not drawn)
J7  SSM-103-S-SV  [Samtec_SSM-103-x-SV]  (value not drawn)
P1  TSW-103-07-T-S  [Samtec_TSW-103-07-T-S]  (value not drawn)
R1  ValueDisplayed: 0  [0201_Silk]  (hidden comment: CRCW02010000Z0ED)
R2  ValueDisplayed: 0  [0201_Silk]  (hidden comment: CRCW02010000Z0ED)
R3  ValueDisplayed: 0  [0201_Silk]  (hidden comment: CRCW02010000Z0ED)
R4  ValueDisplayed: 0  [0201_Silk]  (hidden comment: CRCW02010000Z0ED)
R5  ValueDisplayed: 0  [0201_Silk]  (hidden comment: CRCW02010000Z0ED)
R6  ValueDisplayed: 0  [0201_Silk]  (hidden comment: CRCW02010000Z0ED)
R8  ValueDisplayed: 0  [0201_Silk]  (hidden comment: CRCW02010000Z0ED)
R9  ValueDisplayed: 0  [0201_Silk]  (hidden comment: CRCW02010000Z0ED)
R10  ValueDisplayed: 0  [0201_Silk]  (hidden comment: CRCW02010000Z0ED)
R18  ValueDisplayed: 0  [0201_Silk]  (hidden comment: CRCW02010000Z0ED)
R19  ValueDisplayed: 0  [0201_Silk]  (hidden comment: CRCW02010000Z0ED)
R24  ValueDisplayed: 0  [0201_Silk]  (hidden comment: CRCW02010000Z0ED)
R25  ValueDisplayed: 0  [0201_Silk]  (hidden comment: CRCW02010000Z0ED)
R26  ValueDisplayed: 0  [0201_Silk]  (hidden comment: CRCW02010000Z0ED)
R31  ValueDisplayed: 0  [0201_Silk]  (hidden comment: CRCW02010000Z0ED)
R32  ValueDisplayed: 0  [0201_Silk]  (hidden comment: CRCW02010000Z0ED)
R35  ValueDisplayed: 0  [0201_Silk]  (hidden comment: CRCW02010000Z0ED)
R36  ValueDisplayed: 0  [0201_Silk]  (hidden comment: CRCW02010000Z0ED)
R76  ValueDisplayed: 0  [0201_Silk]  (hidden comment: CRCW02010000Z0ED)
R94  ValueDisplayed: 0  [0201_Silk]  (hidden comment: CRCW02010000Z0ED)
R102  ValueDisplayed: 0  [0201_Silk]  (hidden comment: CRCW02010000Z0ED)
R104  ValueDisplayed: 0  [0201_Silk]  (hidden comment: CRCW02010000Z0ED)
R105  ValueDisplayed: 0  [0201_Silk]  (hidden comment: CRCW02010000Z0ED)
R106  ValueDisplayed: 0  [0201_Silk]  (hidden comment: CRCW02010000Z0ED)
R107  ValueDisplayed: 0  [0402L]  (hidden comment: ERJ-2GE0R00X)
R108  ValueDisplayed: 0  [0201_Silk]  (hidden comment: CRCW02010000Z0ED)
R109  ValueDisplayed: 0  [0201_Silk]  (hidden comment: CRCW02010000Z0ED)
R115  ValueDisplayed: 0  [2010]  (hidden comment: CRCW20100000Z0EF)
R162  ValueDisplayed: 0  [0201_Silk]  (hidden comment: CRCW02010000Z0ED)
R163  ValueDisplayed: 0  [0201_Silk]  (hidden comment: CRCW02010000Z0ED)
R164  ValueDisplayed: 0  [0201_Silk]  (hidden comment: CRCW02010000Z0ED)
R165  ValueDisplayed: 0  [0201_Silk]  (hidden comment: CRCW02010000Z0ED)
R166  ValueDisplayed: 0  [0201_Silk]  (hidden comment: CRCW02010000Z0ED)
R167  ValueDisplayed: 0  [0201_Silk]  (hidden comment: CRCW02010000Z0ED)
R168  ValueDisplayed: 0  [0201_Silk]  (hidden comment: CRCW02010000Z0ED)
R169  ValueDisplayed: 0  [0201_Silk]  (hidden comment: CRCW02010000Z0ED)
R172  ValueDisplayed: 100k  [0402L]  (hidden comment: CRCW0402100KFKED)
R173  ValueDisplayed: 100k  [0402L]  (hidden comment: CRCW0402100KFKED)

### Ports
AR_ANAMUX, AR_ANATEST1, AR_ANATEST2, AR_ANATEST3, AR_ANATEST4, AR_BSS_LOGGER, AR_GPIO_0, AR_GPIO_1, AR_GPIO_2, AR_HOSTINTR1, AR_MCUCLKOUT, AR_MSS_LOGGER, AR_NERR_OUT, AR_NERRIN, AR_NRST_MCU, AR_PMIC_CLKOUT_SOP2, AR_RS232RX, AR_RS232TX, AR_SCL, AR_SDA, AR_SYNC_IN, AR_SYNC_OUT_SOP1, AR_VSENSE, AR_WARMRST, CS1, MCU_SOP0, MCU_SOP1, MCU_SOP2, MISO1, MOSI1, PGOOD, PMIC_EN1, SPICLK1

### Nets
5V_IN: R115.2
+3.3VD: R172.2 R173.2
GND: J4.1 J4.2 J5.4 J6.2 J7.1 J7.2 P1.2
MCU_3V3: J4.3 J5.1
MCU_5V: J5.2 J7.3 R115.1
AR_ANAMUX: P1.3 ; port AR_ANAMUX
AR_ANATEST1: R104.2 ; port AR_ANATEST1
AR_ANATEST2: R94.2 ; port AR_ANATEST2
AR_ANATEST3: R105.2 ; port AR_ANATEST3
AR_ANATEST4: R106.2 ; port AR_ANATEST4
AR_BSS_LOGGER: R31.1 ; port AR_BSS_LOGGER
AR_GPIO_0: R164.1 ; port AR_GPIO_0
AR_GPIO_1: R9.2 ; port AR_GPIO_1
AR_GPIO_2: R8.2 ; port AR_GPIO_2
AR_HOSTINTR1: R10.2 ; port AR_HOSTINTR1
AR_MCUCLKOUT: R25.1 ; port AR_MCUCLKOUT
AR_MSS_LOGGER: R26.1 ; port AR_MSS_LOGGER
AR_NERR_OUT: R19.1 ; port AR_NERR_OUT
AR_NERRIN: R24.1 ; port AR_NERRIN
AR_NRST_MCU: R2.2 ; port AR_NRST_MCU
AR_PMIC_CLKOUT_SOP2: R109.2 ; port AR_PMIC_CLKOUT_SOP2
AR_RS232RX: R166.1 R168.1 R172.1 ; port AR_RS232RX
AR_RS232TX: R167.1 R169.1 R173.1 ; port AR_RS232TX
AR_SCL: R163.1 ; port AR_SCL
AR_SDA: R162.1 ; port AR_SDA
AR_SYNC_IN: R165.1 ; port AR_SYNC_IN
AR_SYNC_OUT_SOP1: R108.2 ; port AR_SYNC_OUT_SOP1
AR_VSENSE: P1.1 ; port AR_VSENSE
AR_WARMRST: R18.1 ; port AR_WARMRST
CS1: R1.2 ; port CS1
D_LOGGER: J6.6 R1.1
MCU_SOP0: R36.1 ; port MCU_SOP0
MCU_SOP1: R35.1 ; port MCU_SOP1
MCU_SOP2: R32.1 ; port MCU_SOP2
MISO1: R3.2 R6.2 ; port MISO1
MOSI1: R4.2 R5.2 ; port MOSI1
PGOOD: R107.2 ; port PGOOD
PMIC_EN1: R102.2 ; port PMIC_EN1
SPICLK1: R76.1 ; port SPICLK1
NetJ5_5: J5.5 R168.2 R169.2
NetJ5_6: J5.6 R104.1
NetJ5_7: J5.7 R166.2 R167.2
NetJ5_8: J5.8 R94.1
NetJ5_9: J5.9 R165.2
NetJ5_10: J5.10 R105.1
NetJ5_12: J5.12 R106.1
NetJ5_13: J5.13 R76.2
NetJ5_14: J5.14 R107.1
NetJ5_15: J5.15 R164.2
NetJ5_16: J5.16 R102.1
NetJ5_17: J5.17 R163.2
NetJ5_18: J5.18 R108.1
NetJ5_19: J5.19 R162.2
NetJ5_20: J5.20 R109.1
NetJ6_1: J6.1 R19.2
NetJ6_3: J6.3 R24.2
NetJ6_5: J6.5 R25.2
NetJ6_8: J6.8 R9.1
NetJ6_9: J6.9 R26.2
NetJ6_10: J6.10 R2.1
NetJ6_11: J6.11 R18.2
NetJ6_12: J6.12 R4.1 R5.1
NetJ6_13: J6.13 R31.2
NetJ6_14: J6.14 R3.1 R6.1
NetJ6_15: J6.15 R32.2
NetJ6_16: J6.16 R10.1
NetJ6_17: J6.17 R35.2
NetJ6_18: J6.18 R8.1
NetJ6_19: J6.19 R36.2

Not connected (* = marked no-connect by the designer): J5 3* 11*; J6 4* 7* 20*

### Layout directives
net class GENERAL: (no net found under the mark), NetJ6_8, NetJ6_10, NetJ6_18
net class CLK: NetJ5_20, NetJ6_5
net class PWR: MCU_3V3, MCU_5V
net class SPI: D_LOGGER, NetJ5_13, NetJ6_12, NetJ6_14, NetJ6_16

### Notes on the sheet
- BP/LP CONNECTOR
- (near P1) ANALOG SIGNALS

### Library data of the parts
J4 J7 = CMP-0078183-1: Receptacle, 2.54mm, 3x1, Gold with Tin tail, SMT; Manufacturer: Samtec; Pitch_mm: 2.54; Gender: Female; Cert_CSA: Y; Voltage_V: 405V; Current_A: 5.2A; Row_Count: 1; CompType: Socket Strip
J5 J6 = CMP-0078182-1: Receptacle, 2.54mm, 10x2, Gold with Tin tail, SMT; Manufacturer: Samtec; Pitch_mm: 2.54; Gender: Female; Cert_CSA: Y; Voltage_V: 405V; Current_A: 5.2A; Row_Count: 2; CompType: Socket Strip
P1 = CMP-0075530-2: Header, 2.54 mm, 3x1, Tin, TH; Manufacturer: Samtec; Pitch_mm: 2.54; Cert_VDE: N; Gender: Male; Cert_CSA: Y; Voltage_V: 550V; Green_REACh: Passed; Current_A: 6.3A; Green_Lifecycle: Active; Row_Count: 1
R1-R6 R8-R10 R18 R19 R24-R26 R31 R32 R35 R36 R94 R102 R105 R106 R108 R109 R162-R169 = CMP-0027008-4: as R72 on sheet PROC010C_Pwr_RST_LEDs
R76 R104 = CMP-0027008-4: RES, 0, 5%, 0.05 W, 0201; Manufacturer: Vishay-Dale; Power_W: 50mW; TempCo: ppm/C; Value_Code: 0000; Value: 0; EIA_Code: E24; SizeX_mm: 0.6; SizeY_mm: 0.3; SizeZ_mm: 0.26; Value2: 0.05W; SizeArea_mm2: 0.18; CompType: Resistor; AEC Qualified: N; AEC Category: Q200
R107 = CMP-0026992-2: as R119 on sheet PROC010C_LDO
R115 = CMP-0016044-3: as R118 on sheet PROC010C_Pwr_RST_LEDs
R172 R173 = CMP-0025950-3: as R110 on sheet PROC010C_Pwr_RST_LEDs

## Sheet PROC010C_XDS110 Interface_1A.SchDoc: XDS110 Interface_1A
size 431 x 279 mm; Date: Not shown in title block; ApprovedBy: Not shown in title block; CheckedBy: Not shown in title block; Author: Not shown in title block; CompanyName: Not shown in title block; DrawnBy: Adrian Ozer; Engineer: Not shown in title block; Organization: Not shown in title block; Address1: Not shown in title block; Address2: Not shown in title block; Address3: Not shown in title block; Address4: Not shown in title block; DocumentNumber: 12; Revision: Use project parameter SCH_Rev; SheetNumber: 12; SheetTotal: 16; PageSetup: Record=PageOptions¦CenterHorizontal=True¦CenterVertical=True¦PrintScale=1.00¦XCorrection=1.00¦YCorrection=1.00¦PrintKind=0¦BorderSize=5000000¦LeftOffset=0¦BottomOffset=0¦Orientation=2¦PaperLength=1000¦PaperWidth=1000¦Scale=100¦PaperSource=15¦PrintQuality=600¦MediaType=1¦DitherType=10¦PaperKind=Letter¦PrintScaleMode=1
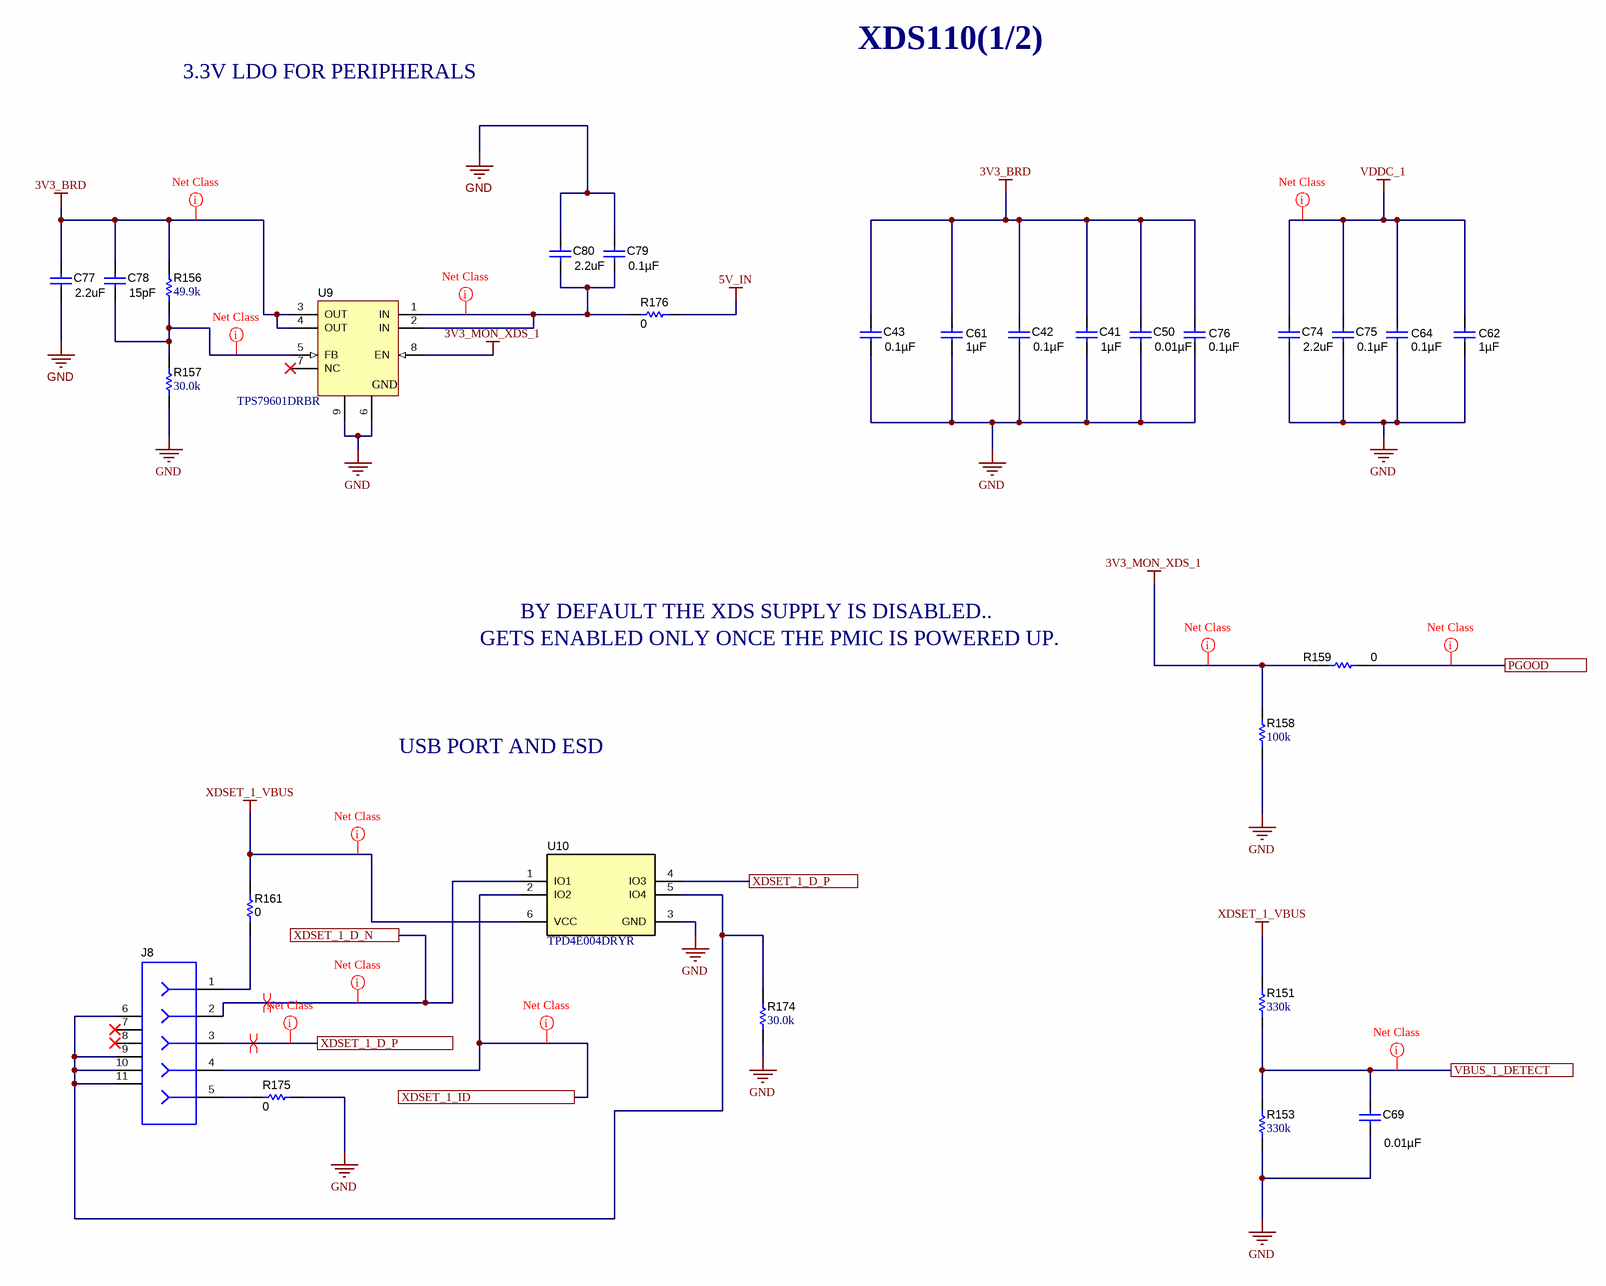
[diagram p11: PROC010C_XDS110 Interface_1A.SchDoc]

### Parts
C41  ValueDisplayed: 1µF  [0402L]  (hidden comment: C1005X7S0J105M050BC)
C42  ValueDisplayed: 0.1µF  [0402L]  (hidden comment: C0402C104K8RACTU)
C43  ValueDisplayed: 0.1µF  [0402L]  (hidden comment: C0402C104K8RACTU)
C50  ValueDisplayed: 0.01µF  [0402L]  (hidden comment: C1005X7R1E103K050BB)
C61  ValueDisplayed: 1µF  [0402L]  (hidden comment: C1005X7S0J105M050BC)
C62  ValueDisplayed: 1µF  [0402L]  (hidden comment: C1005X7S0J105M050BC)
C64  ValueDisplayed: 0.1µF  [0402L]  (hidden comment: C0402C104K8RACTU)
C69  ValueDisplayed: 0.01µF  [0402L]  (hidden comment: C0402C103K4RACTU)
C74  ValueDisplayed: 2.2uF  [0402_065L]  (hidden comment: C1005X7S1A225K050BC)
C75  ValueDisplayed: 0.1µF  [0402L]  (hidden comment: C0402C104K8RACTU)
C76  ValueDisplayed: 0.1µF  [0402L]  (hidden comment: C0402C104K8RACTU)
C77  ValueDisplayed: 2.2uF  [0402_065L]  (hidden comment: C1005X7S1A225K050BC)
C78  ValueDisplayed: 15pF  [0402L]  (hidden comment: 04025A150FAT2A)
C79  ValueDisplayed: 0.1µF  [0402L]  (hidden comment: C0402C104K8RACTU)
C80  ValueDisplayed: 2.2uF  [0402_065L]  (hidden comment: C1005X7S1A225K050BC)
J8  105017-0001  [CONN_105017-0001]  (value not drawn)
R151  ValueDisplayed: 330k  [0402L]  (hidden comment: CRCW0402330KFKED)
R153  ValueDisplayed: 330k  [0402L]  (hidden comment: CRCW0402330KFKED)
R156  ValueDisplayed: 49.9k  [0402L]  (hidden comment: CRCW040249K9FKED)
R157  ValueDisplayed: 30.0k  [0402L]  (hidden comment: CRCW040230K0FKED)
R158  ValueDisplayed: 100k  [0402L]  (hidden comment: CRCW0402100KFKED)
R159  ValueDisplayed: 0  [0402L]  (hidden comment: ERJ-2GE0R00X)
R161  ValueDisplayed: 0  [0603]  (hidden comment: MCT06030Z0000ZP500)
R174  ValueDisplayed: 30.0k  [0402L]  (hidden comment: CRCW040230K0FKED)
R175  ValueDisplayed: 0  [0603]  (hidden comment: MCT06030Z0000ZP500)
R176  ValueDisplayed: 0  [0603]  (hidden comment: MCT06030Z0000ZP500)
U9  TPS79601DRBR  [DRB0008B]
U10  TPD4E004DRYR  [DRY0006A]

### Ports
PGOOD, VBUS_1_DETECT, XDSET_1_D_N, XDSET_1_D_P, XDSET_1_ID

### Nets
3V3_BRD: C41.2 C42.2 C43.2 C50.2 C61.2 C76.2 C77.2 C78.2 R156.2 U9.3(OUT) U9.4(OUT)
3V3_MON_XDS_1: R158.2 R159.2 U9.8(EN)
5V_IN: R176.2
GND: C41.1 C42.1 C43.1 C50.1 C61.1 C62.1 C64.1 C69.1 C74.1 C75.1 C76.1 C77.1 C79.1 C80.1 R153.1 R157.1 R158.1 R174.1 R175.1 U9.6(GND) U9.9(GND) U10.3(GND)
VDDC_1: C62.2 C64.2 C74.2 C75.2
XDSET_1_VBUS: R151.2 R161.2 U10.6(VCC)
PGOOD: R159.1 ; port PGOOD
VBUS_1_DETECT: C69.2 R151.1 R153.2 ; port VBUS_1_DETECT
XDSET_1_D_N: J8.2 U10.1(IO1) ; port XDSET_1_D_N
XDSET_1_D_P: J8.3 U10.4(IO3) ; port XDSET_1_D_P
XDSET_1_ID: J8.4 U10.2(IO2) ; port XDSET_1_ID
NetC78_1: C78.1 R156.1 R157.2 U9.5(FB)
NetC79_2: C79.2 C80.2 R176.1 U9.1(IN) U9.2(IN)
NetJ8_1: J8.1 R161.1
NetJ8_5: J8.5 R175.2
NetJ8_6: J8.6 J8.9 J8.10 J8.11 R174.2 U10.5(IO4)

Not connected (* = marked no-connect by the designer): J8 7* 8*; U9 7(NC)*

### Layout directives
differential pair: XDSET_1_D_N, XDSET_1_D_P
net class PWR: 3V3_BRD, 3V3_MON_XDS_1, NetC78_1, NetC79_2, VDDC_1, XDSET_1_VBUS
net class USB: XDSET_1_D_N, XDSET_1_D_P
net class GENERAL: PGOOD, VBUS_1_DETECT, XDSET_1_ID

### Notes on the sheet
- XDS110(1/2)
- 3.3V LDO FOR PERIPHERALS
- GETS ENABLED ONLY ONCE THE PMIC IS POWERED UP.
- BY DEFAULT THE XDS SUPPLY IS DISABLED..
- USB PORT AND ESD

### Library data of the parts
C41 C61 C62 = CMP-0078222-1: CAP, CERM, 1 µF, 6.3 V,+/- 20%, X7S, 0402; Manufacturer: TDK; TaMin_C: -55°C; Polarized: N; SizeAreaWB_mm2: 3; U/M: EA; Value: 1uF; TaMax_C: 125°C; SizeZ_mm: 0.6; SizeX_mm: 1; SizeY_mm: 0.5; Cap_Case: 0402; Value2: 6.3V; AEC Category: Q200
C42 C43 C64 C75 C76 C79 = CMP-0078241-1: CAP, CERM, 0.1 µF, 10 V,+/- 10%, X7R, 0402; Manufacturer: Kemet; TaMin_C: -55°C; Polarized: N; SizeAreaWB_mm2: 3; U/M: EA; Value: 0.1uF; TaMax_C: 125°C; SizeZ_mm: 0.6; SizeX_mm: 1; SizeY_mm: 0.5; Cap_Case: 0402; Value2: 10V; Cap_F: 100nF; AEC Category: Q200
C50 = CMP-0078220-1: CAP, CERM, 0.01 µF, 25 V,+/- 10%, X7R, 0402; Manufacturer: TDK; TaMin_C: -55°C; Polarized: N; Green_Lifecycle: NRND; SizeAreaWB_mm2: 3; Green_REACh: Passed; U/M: EA; Value: 0.01uF; TaMax_C: 125°C; SizeZ_mm: 0.6; SizeX_mm: 1; SizeY_mm: 0.5; Cap_Case: 0402; Value2: 25V; Cap_F: 10nF; AEC Category: Q200
C69 = CMP-0078218-1: CAP, CERM, 0.01 µF, 16 V,+/- 10%, X7R, 0402; Manufacturer: Kemet; TaMin_C: -55°C; Polarized: N; Green_Lifecycle: Active; SizeAreaWB_mm2: 3; Green_REACh: Passed; U/M: EA; Value: 0.01uF; TaMax_C: 125°C; SizeZ_mm: 0.6; SizeX_mm: 1; SizeY_mm: 0.5; Cap_Case: 0402; Value2: 16V; Cap_F: 10nF; AEC Category: Q200
C74 C77 C80 = CMP-0006302-2: CAP, CERM, 2.2 uF, 10 V, +/- 10%, X7S, 0402; Manufacturer: TDK; TaMin_C: -55°C; ESR_ohm: 5.925m; Polarized: N; SizeAreaWB_mm2: 3; Value1: 0.005925 ohm; U/M: EA; Value: 2.2uF; TaMax_C: 125°C; SizeZ_mm: 0.65; SizeX_mm: 1; SizeY_mm: 0.5; Cap_Case: 0402_065; Value2: 10V; CompType: Capacitor; Cap_F: 2.2µF; IRMS_A: 2.05591A; AEC Category: Q200
C78 = CMP-0078217-1: CAP, CERM, 15 pF, 50 V,+/- 1%, C0G/NP0, 0402; Manufacturer: AVX; TaMin_C: -55°C; Polarized: N; Green_Lifecycle: Not Set; SizeAreaWB_mm2: 3; Green_REACh: Incomplete; U/M: EA; Value: 15pF; TaMax_C: 125°C; SizeZ_mm: 0.6; SizeX_mm: 1; SizeY_mm: 0.5; Cap_Case: 0402; Value2: 50V; AEC Category: Q200
J8 = CMP-0055293-1: Connector, Receptacle, Micro-USB Type B, R/A, Bottom Mount SMT; Manufacturer: Molex; CNHeader: FALSE; Green_Lifecycle: Active; Gender: Female; Green_REACh: Passed; CompType: USB; CT: TRUE
R151 R153 = CMP-0078210-2: RES, 330 k, 1%, 0.063 W, AEC-Q200 Grade 0, 0402; Manufacturer: Vishay-Dale; SizeArea_mm2: 0.5; AEC Qualified: Y; AEC Category: Q200; Value: 330k; SizeZ_mm: 0.6; TempCo: 100 ppm/C; AEC Grade: 0; Power_W: 63mW; VDC_V: 50V; Value2: 0.063W; SizeX_mm: 1
R156 = CMP-0026403-2: RES, 49.9 k, 1%, 0.063 W, AEC-Q200 Grade 0, 0402; Manufacturer: Vishay-Dale; Power_W: 63mW; TempCo: 100 ppm/C; Value_Code: 49k9; Value: 49.9k; EIA_Code: E96; SizeX_mm: 1; SizeY_mm: 0.5; SizeZ_mm: 0.6; Value2: 0.063W; AEC Qualified: Y; VDC_V: 50V; AEC Category: Q200; AEC Grade: 0
R157 R174 = CMP-0078244-2: RES, 30.0 k, 1%, 0.063 W, AEC-Q200 Grade 0, 0402; Manufacturer: Vishay-Dale; Power_W: 63mW; Green_Lifecycle: Active; TempCo: 100 ppm/C; Value_Code: 30k0; Green_REACh: Passed; Value: 30.0k; Res_ohm: 30k; SizeX_mm: 1; SizeY_mm: 0.5; SizeZ_mm: 0.6; Value2: 0.063W; AEC Qualified: Y; VDC_V: 50V; AEC Grade: 0; AEC Category: Q200
R158 = CMP-0025950-3: as R110 on sheet PROC010C_Pwr_RST_LEDs
R159 = CMP-0026992-2: as R119 on sheet PROC010C_LDO
R161 R175 R176 = CMP-0025884-3: as R133 on sheet PROC010C_Pwr_RST_LEDs
U9 = CMP-0036402-3: Single Output High PSRR LDO, 1 A, Adjustable 1.2 to 5.5 V Output, 2.7 to 5.5 V Input, 8-pin SON (DRB), -40 to 125 degC, Green (RoHS & no Sb/Br); Manufacturer: Texas Instruments; Vin(Min)(V): 2.7; Vout Adj(Max)(V): 5.5; Vout Adj(Min)(V): 1.2; Accuracy(%): 2; SubFamily: Single Channel LDO; Iq(Typ)(mA): 0.26; Vdo(Typ)(mV): 250; Iout(Max)(A): 1; AEC Category: Q200; AEC Qualified: N; CompType: IC; SizeArea_mm2: 9.0; SizeAreaWB_mm2: 16.0; SizeX_mm: 3.0; SizeZ_mm: 1.0
U10 = CMP-0043115-2: ESD-Protection Array for High-Speed Data Interfaces, 4 Channels, -40 to +85 degC, 6-pin SON (DRY), Green (RoHS & no Sb/Br); Manufacturer: Texas Instruments; IO Leakage Current(nA): 1; USB High Speed: TRUE; IO Capacitance(Typ)(pF): 1.6; SubFamily: ESD Solution; IEC 61000-4-2 Contact(+/- kV): 8; Breakdown Voltage(Min)(V): 6; IEC 61000-4-2 Air-Gap(+/- kV): 12; AEC Category: Q200; AEC Qualified: N; CompType: IC; SizeArea_mm2: 1.45; SizeAreaWB_mm2: 4.9; SizeX_mm: 1.0; SizeZ_mm: 0.6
